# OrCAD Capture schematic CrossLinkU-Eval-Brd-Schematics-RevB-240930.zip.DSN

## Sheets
1 09 Revision History: title: Revision History; rev: 1.0; note: 305-PD-24-0940
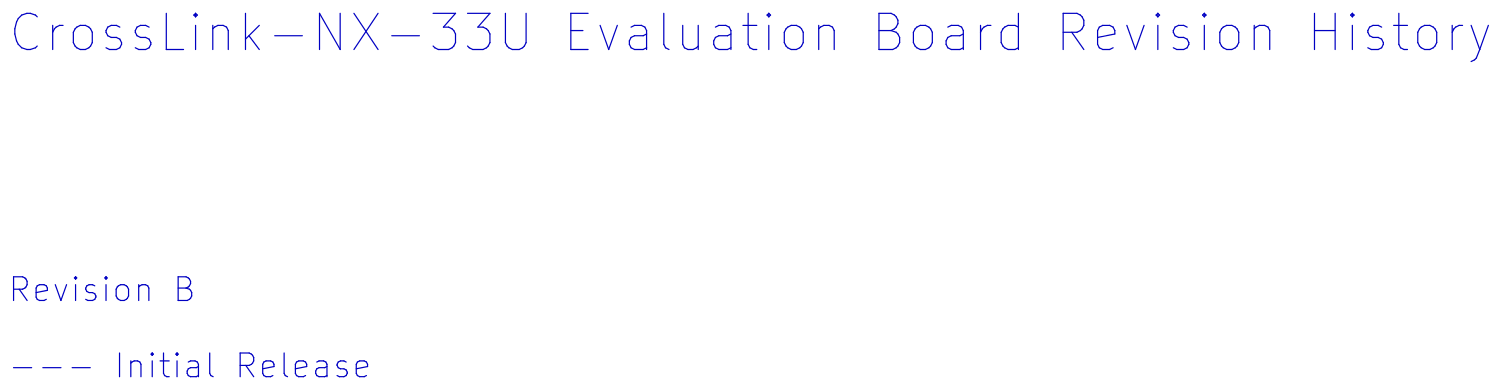
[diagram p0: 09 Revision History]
2 01 Title Page: title: Title Page
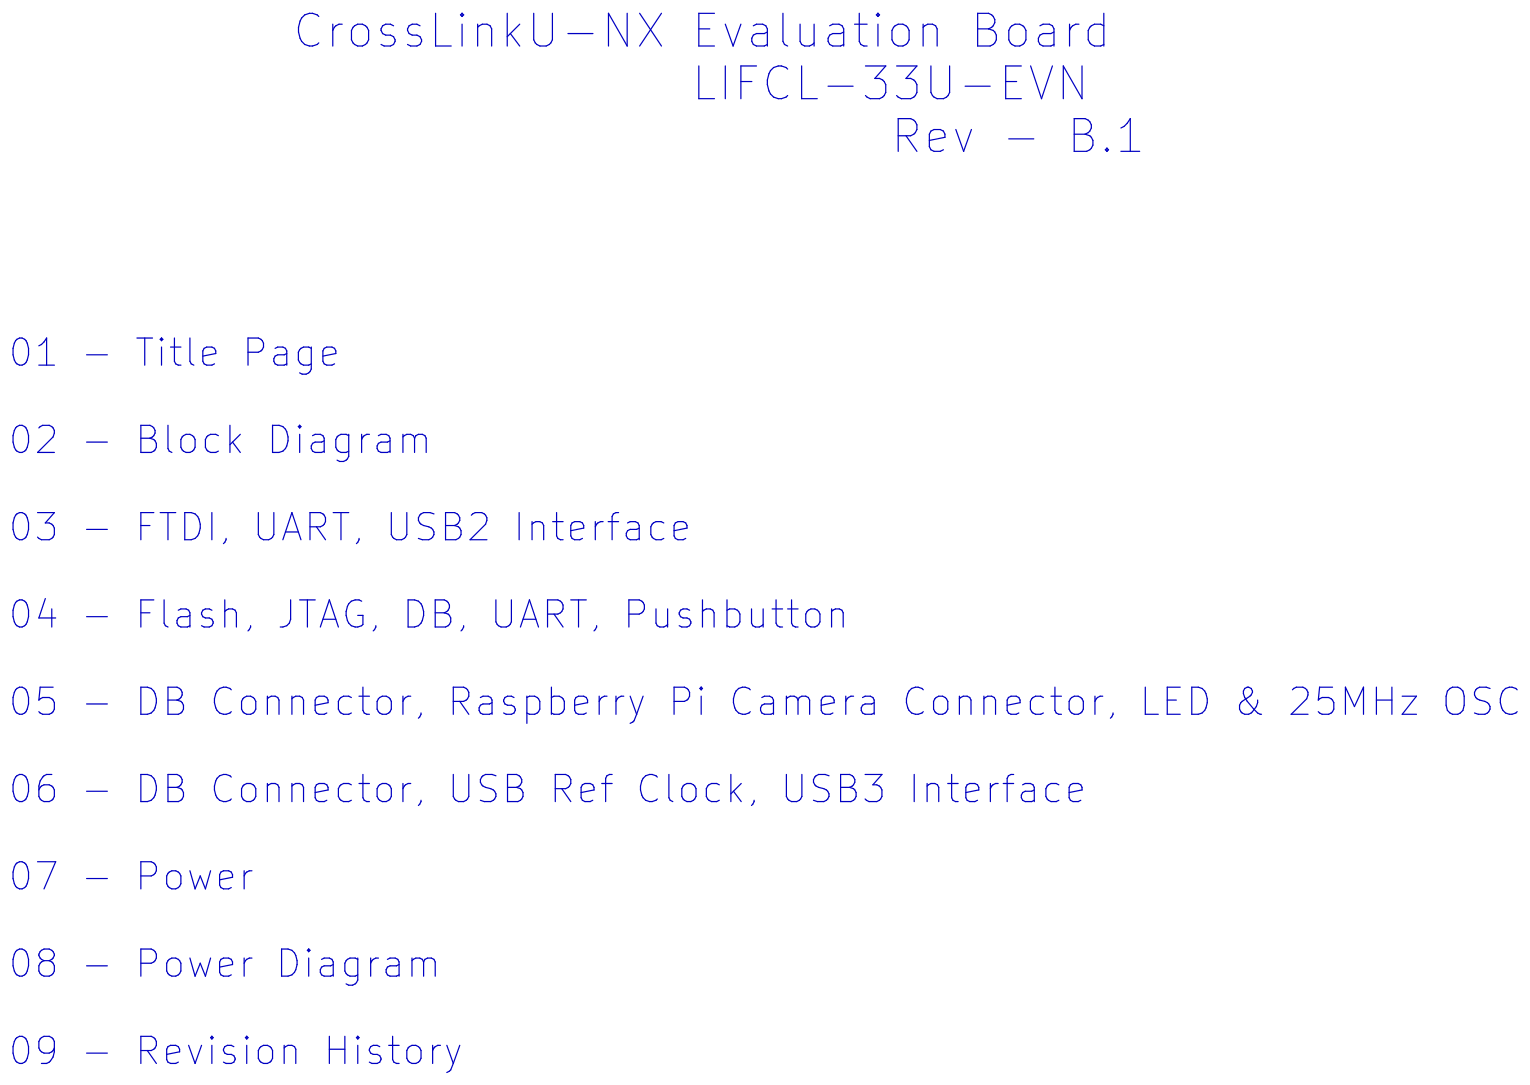
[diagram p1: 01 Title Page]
3 02 Block Diagram: title: Block Diagram
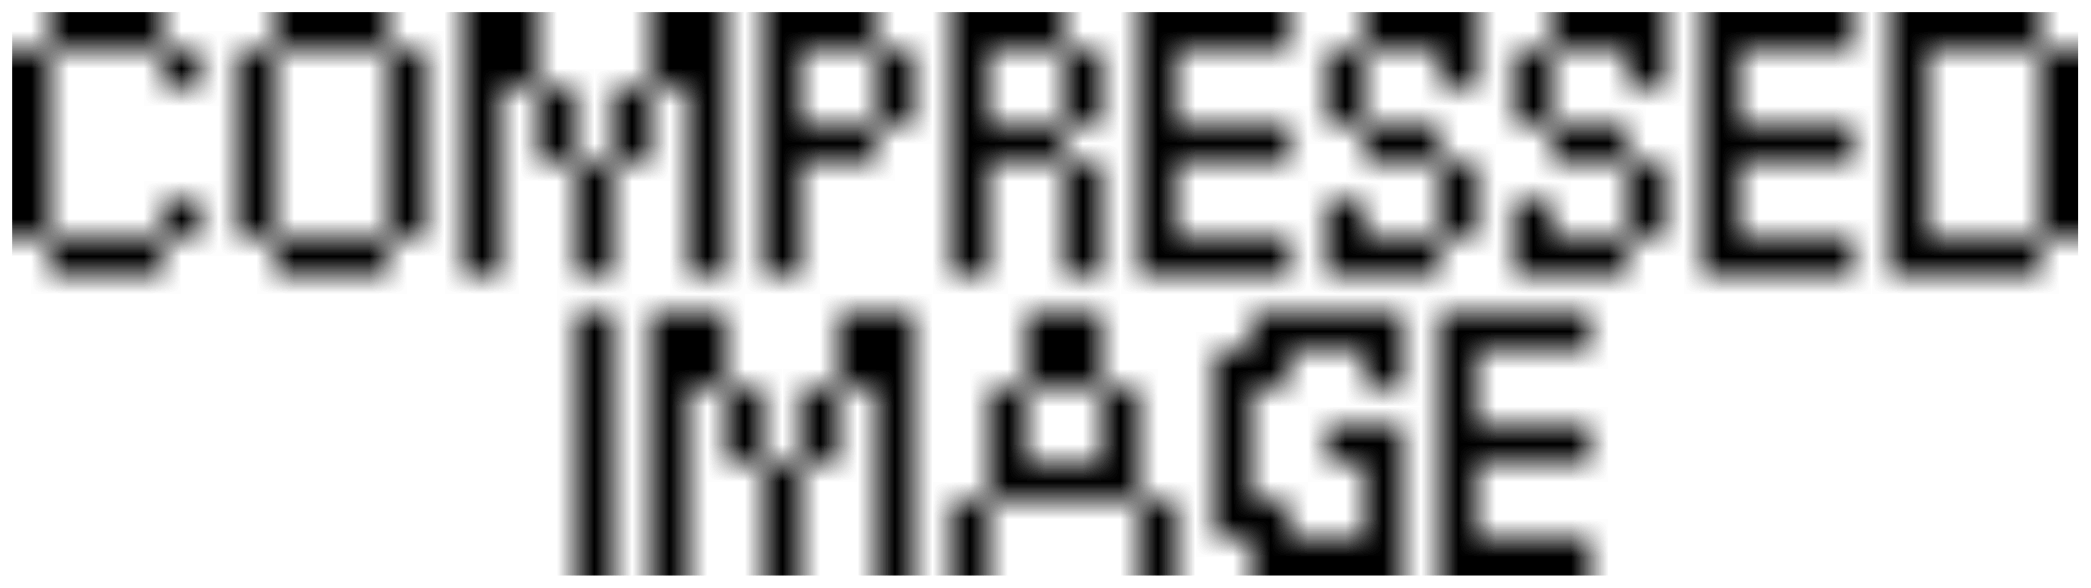
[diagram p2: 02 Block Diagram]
4 04 Flash, JTAG, LED, USB3, PMOD: size C; title: Flash, JTAG, DB, UART, Push Button
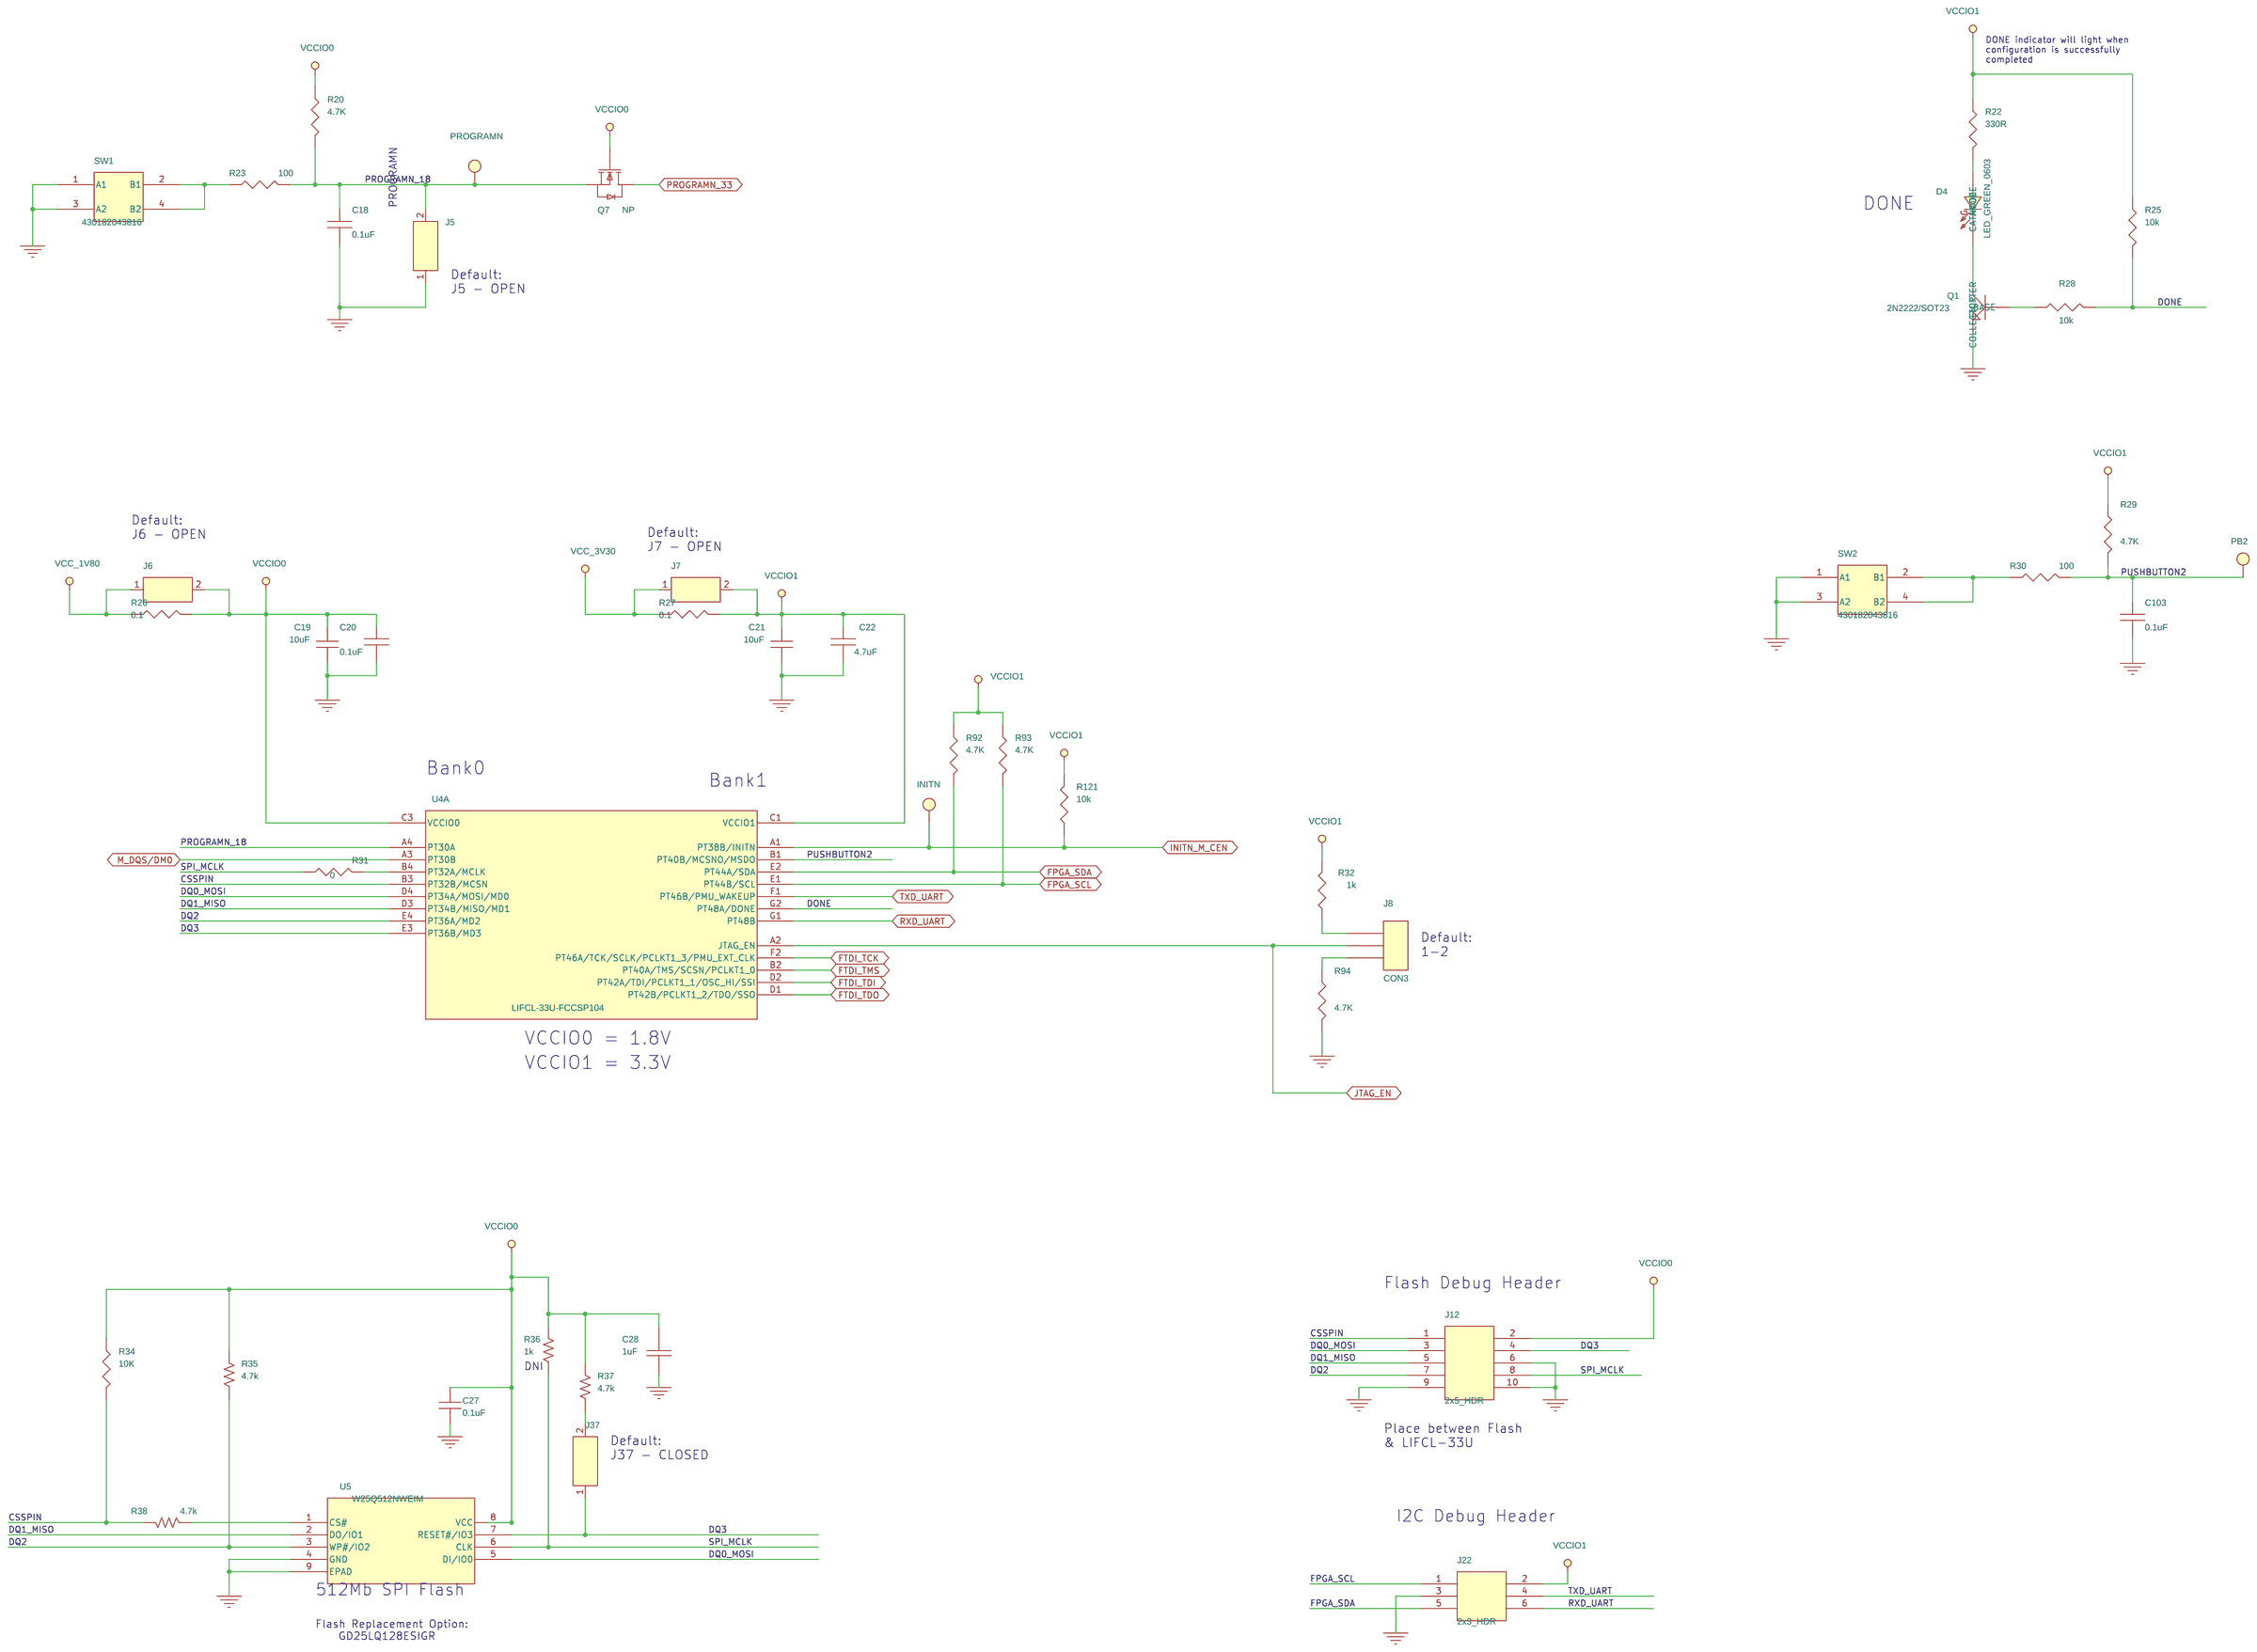
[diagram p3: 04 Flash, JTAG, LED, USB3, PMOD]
5 05 MIPI, PMOD: size C; title: DB Connector, Raspberry Pi Camera Connector, LED & 25MHz OSC
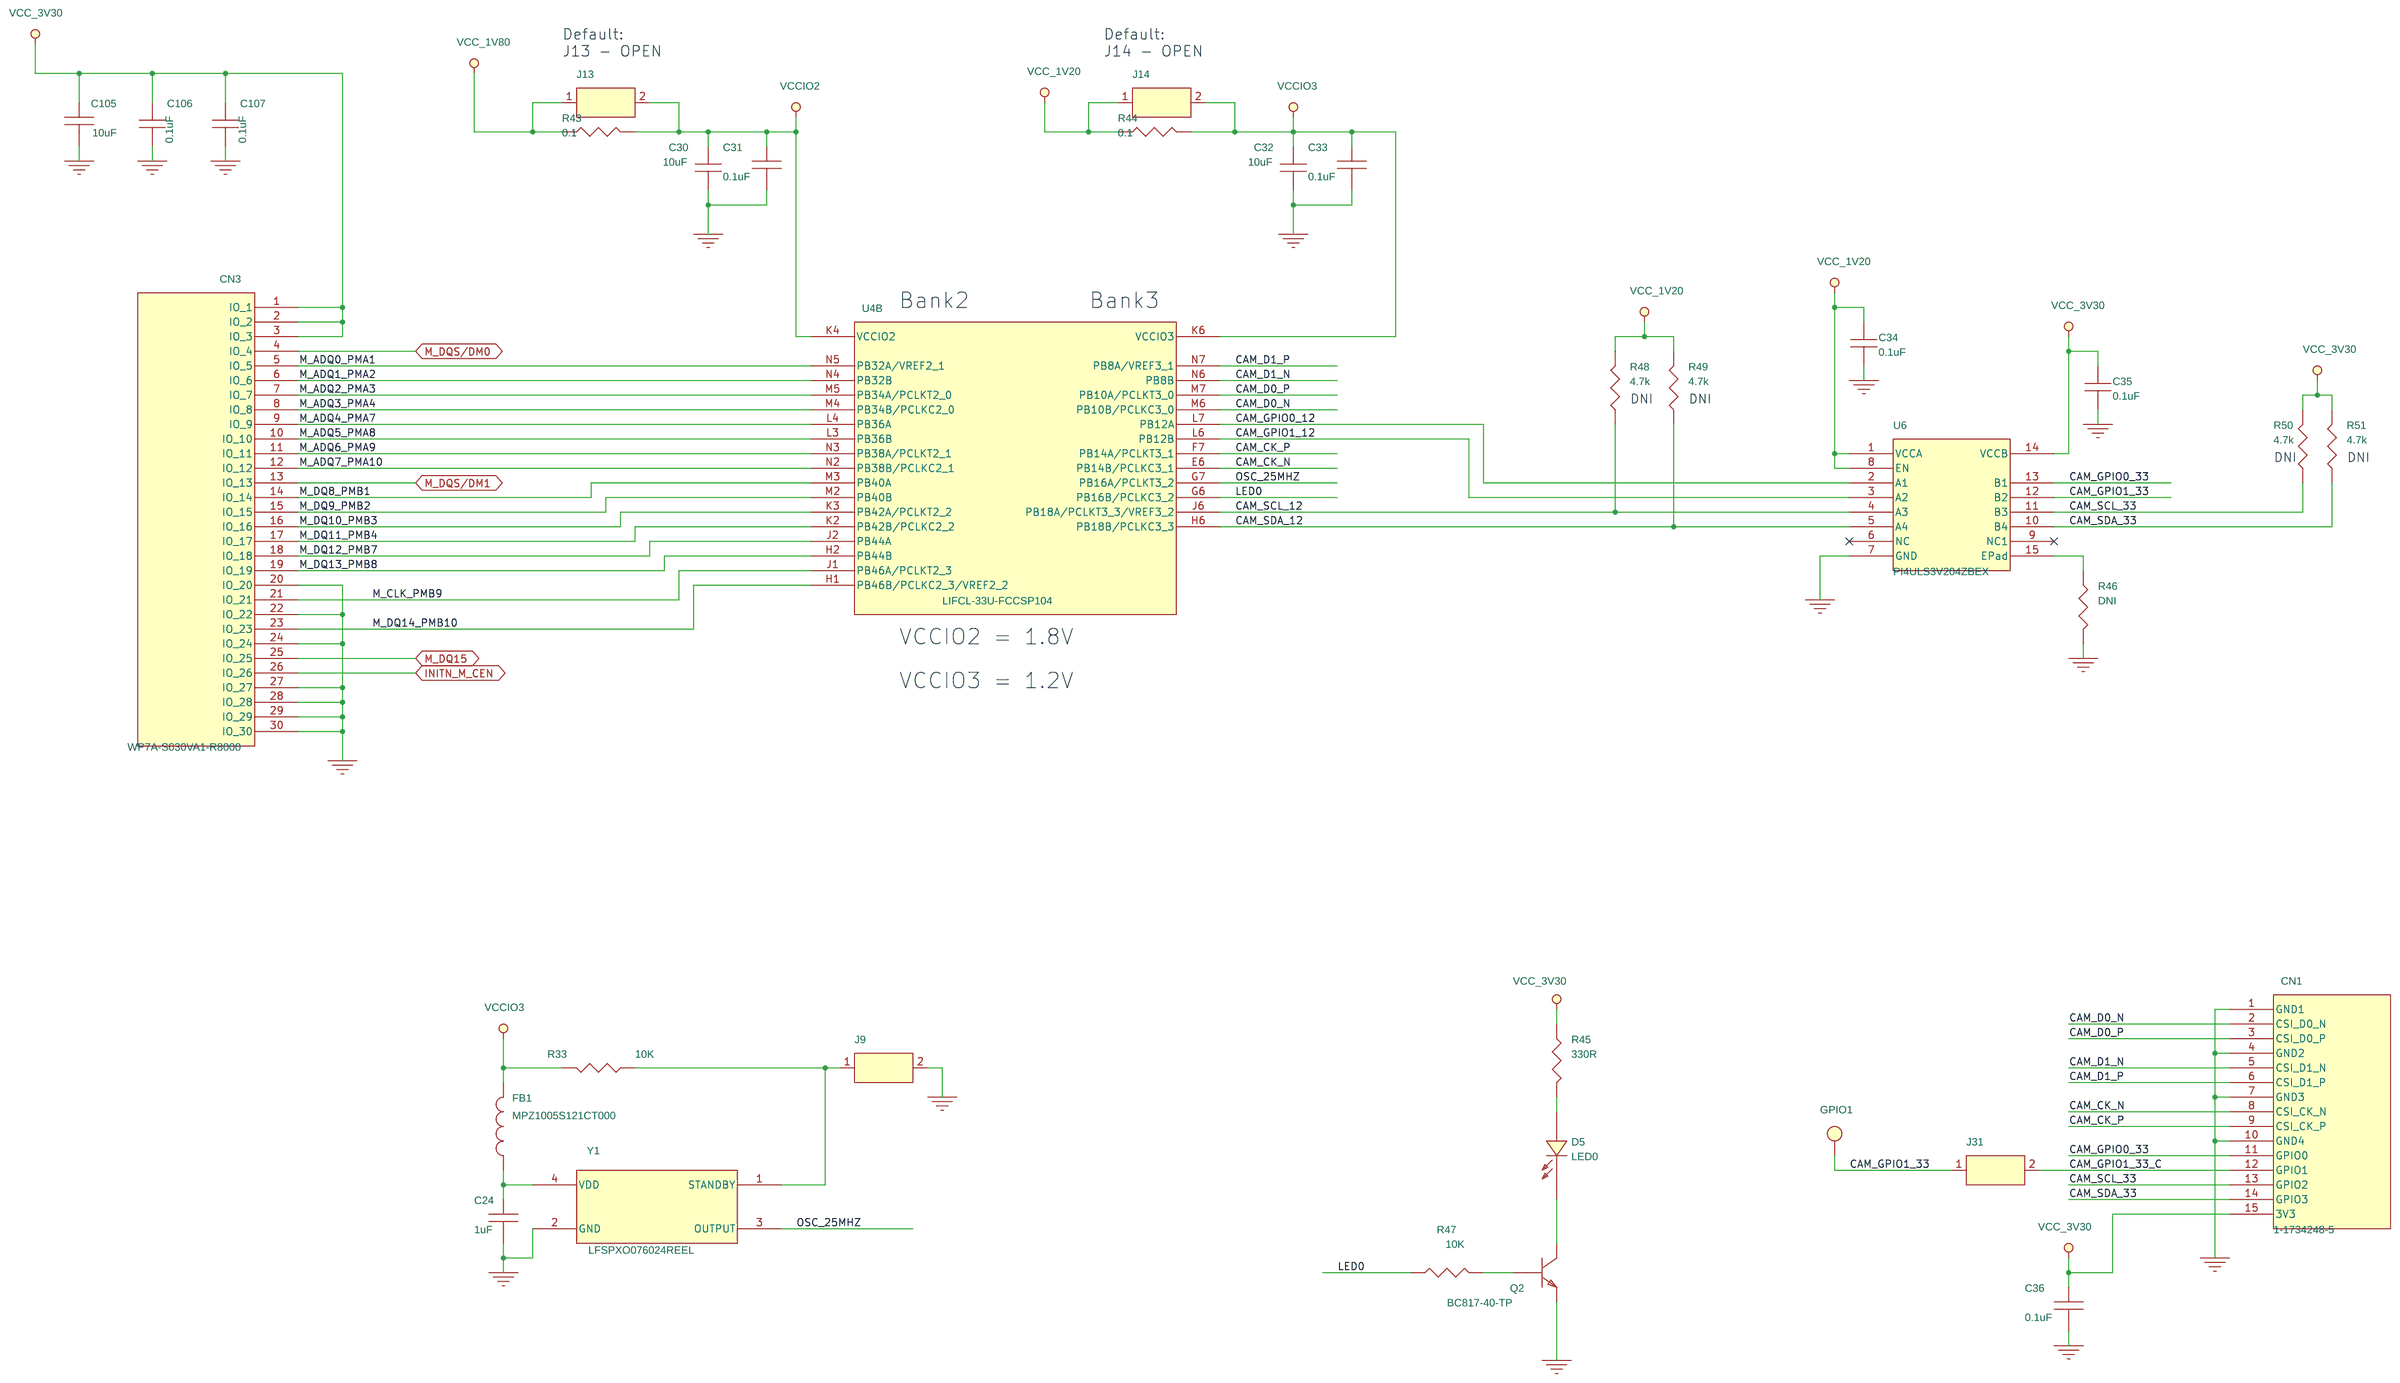
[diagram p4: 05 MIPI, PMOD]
6 06 USB3: size C; title: DB Connector, USB Ref Clock & USB3 Interface
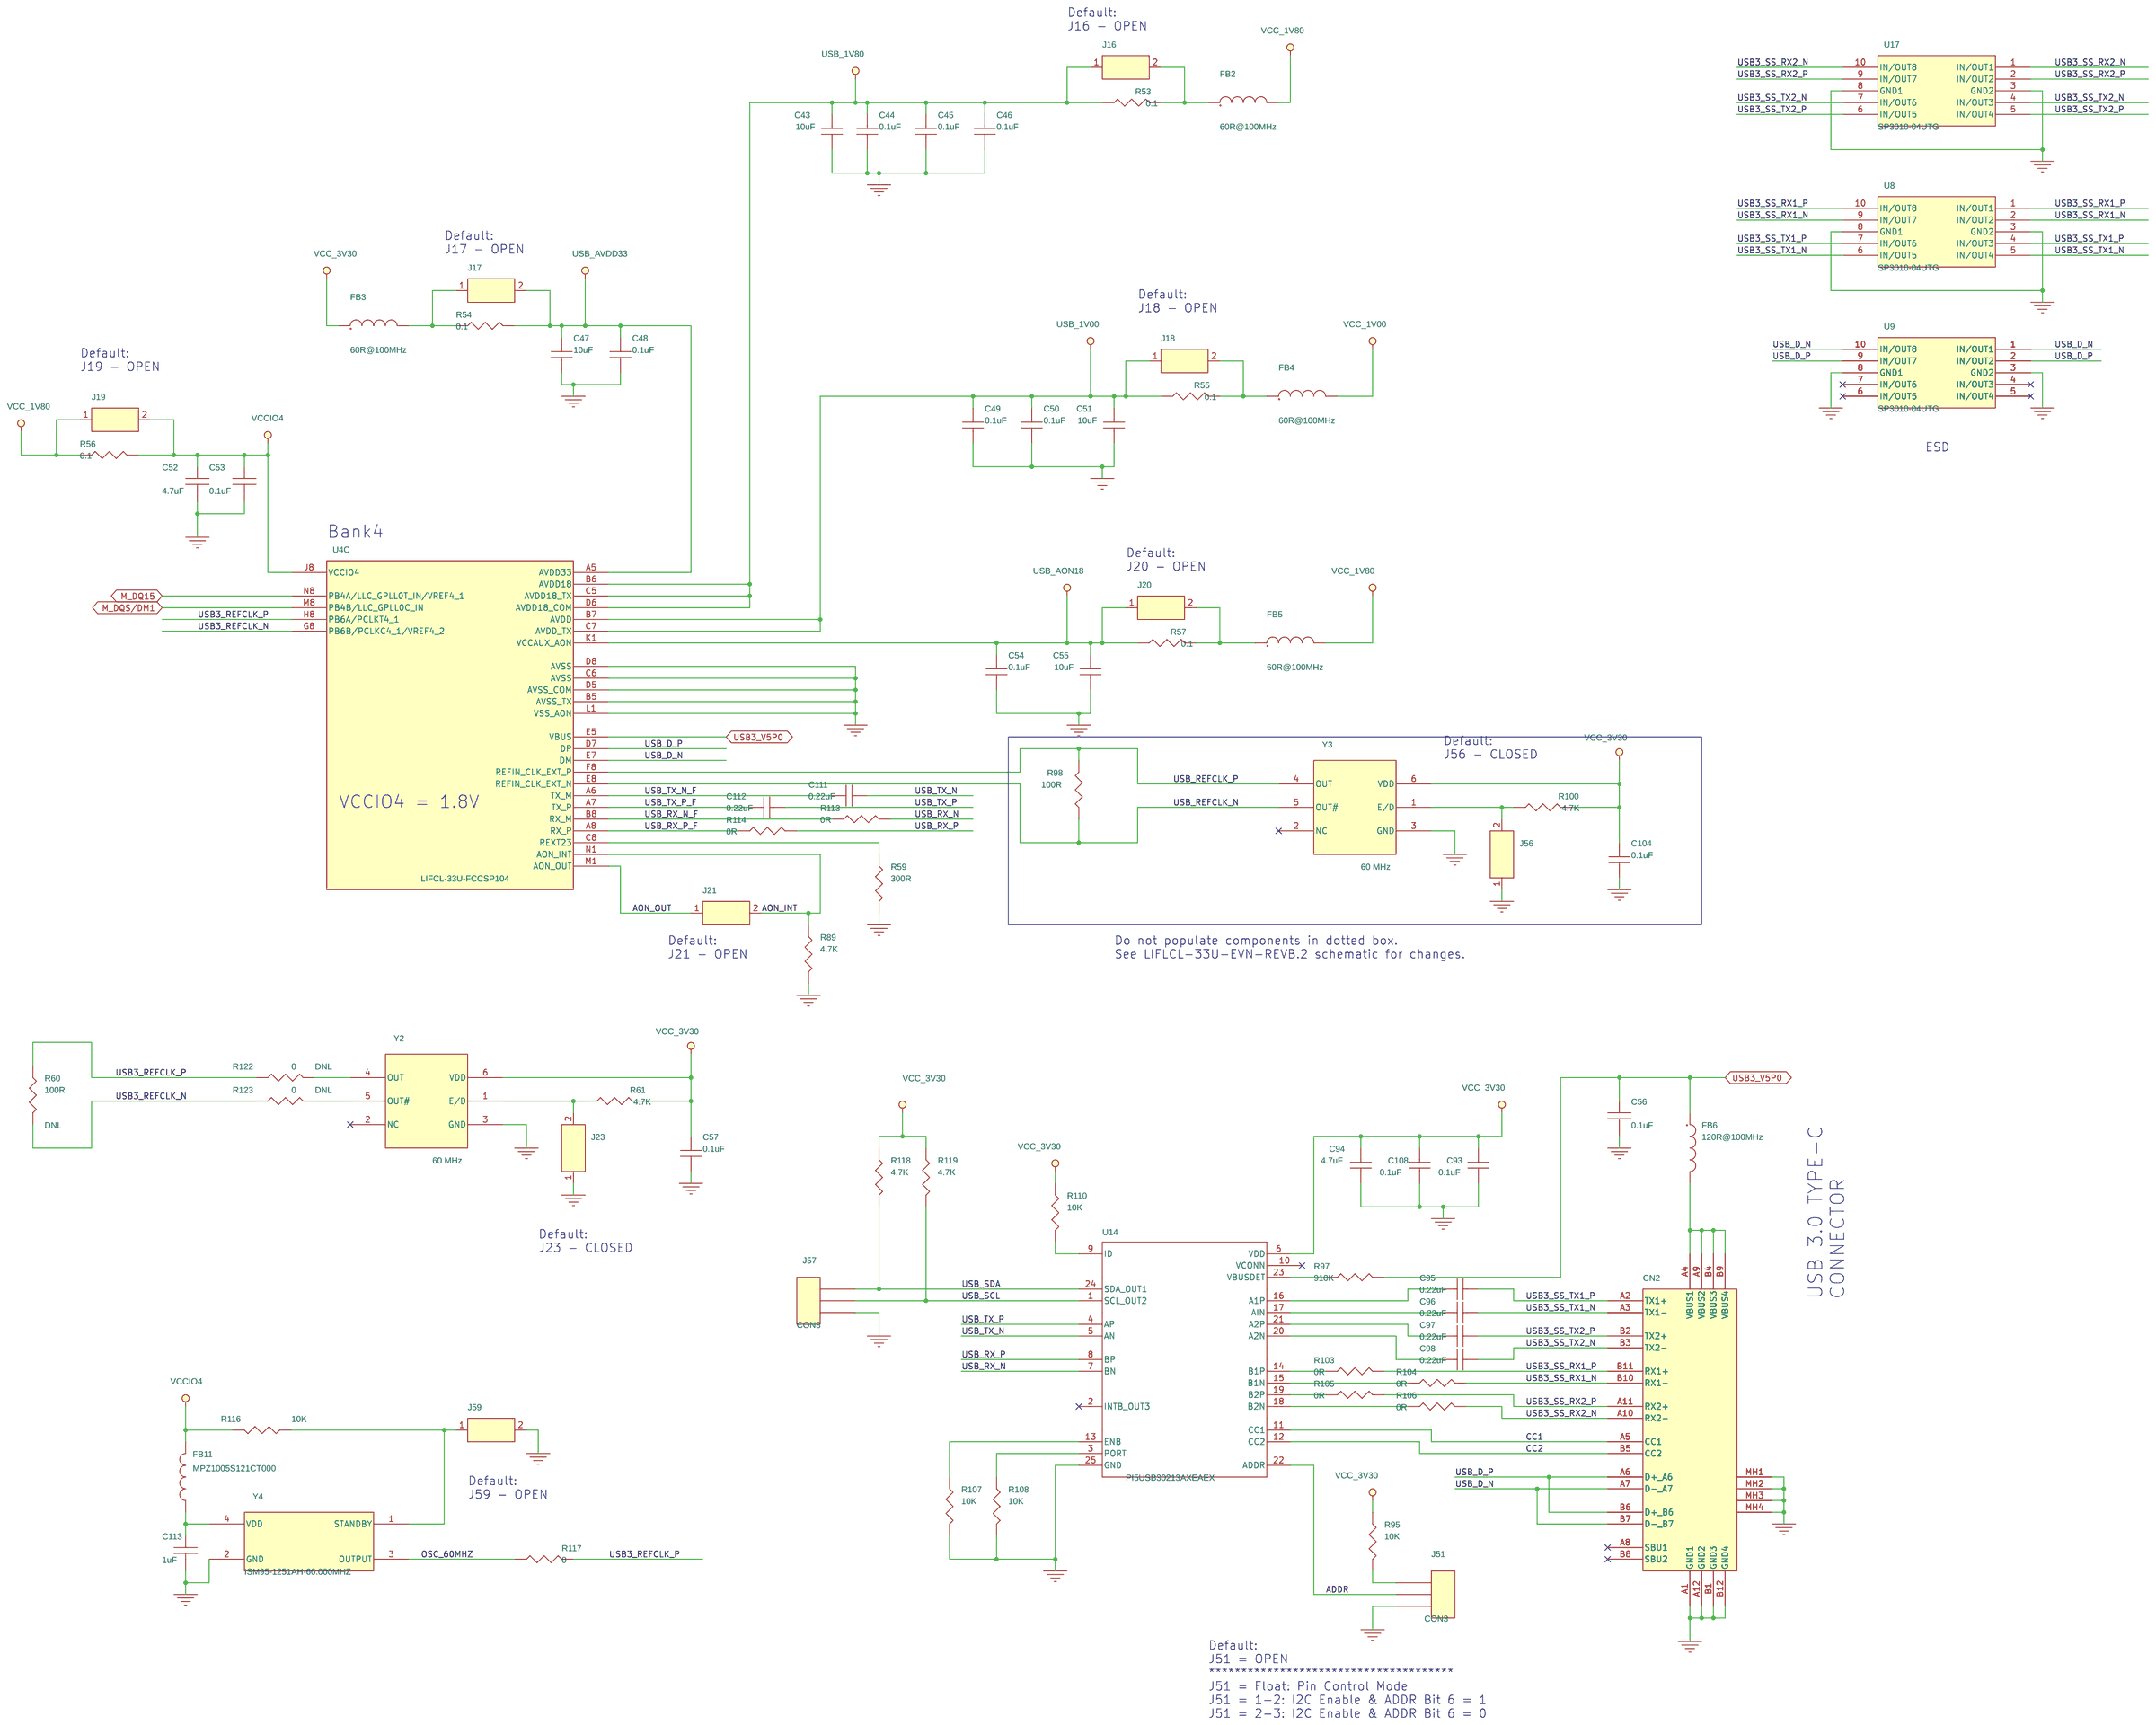
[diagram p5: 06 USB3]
7 07 Power: size C; title: Power
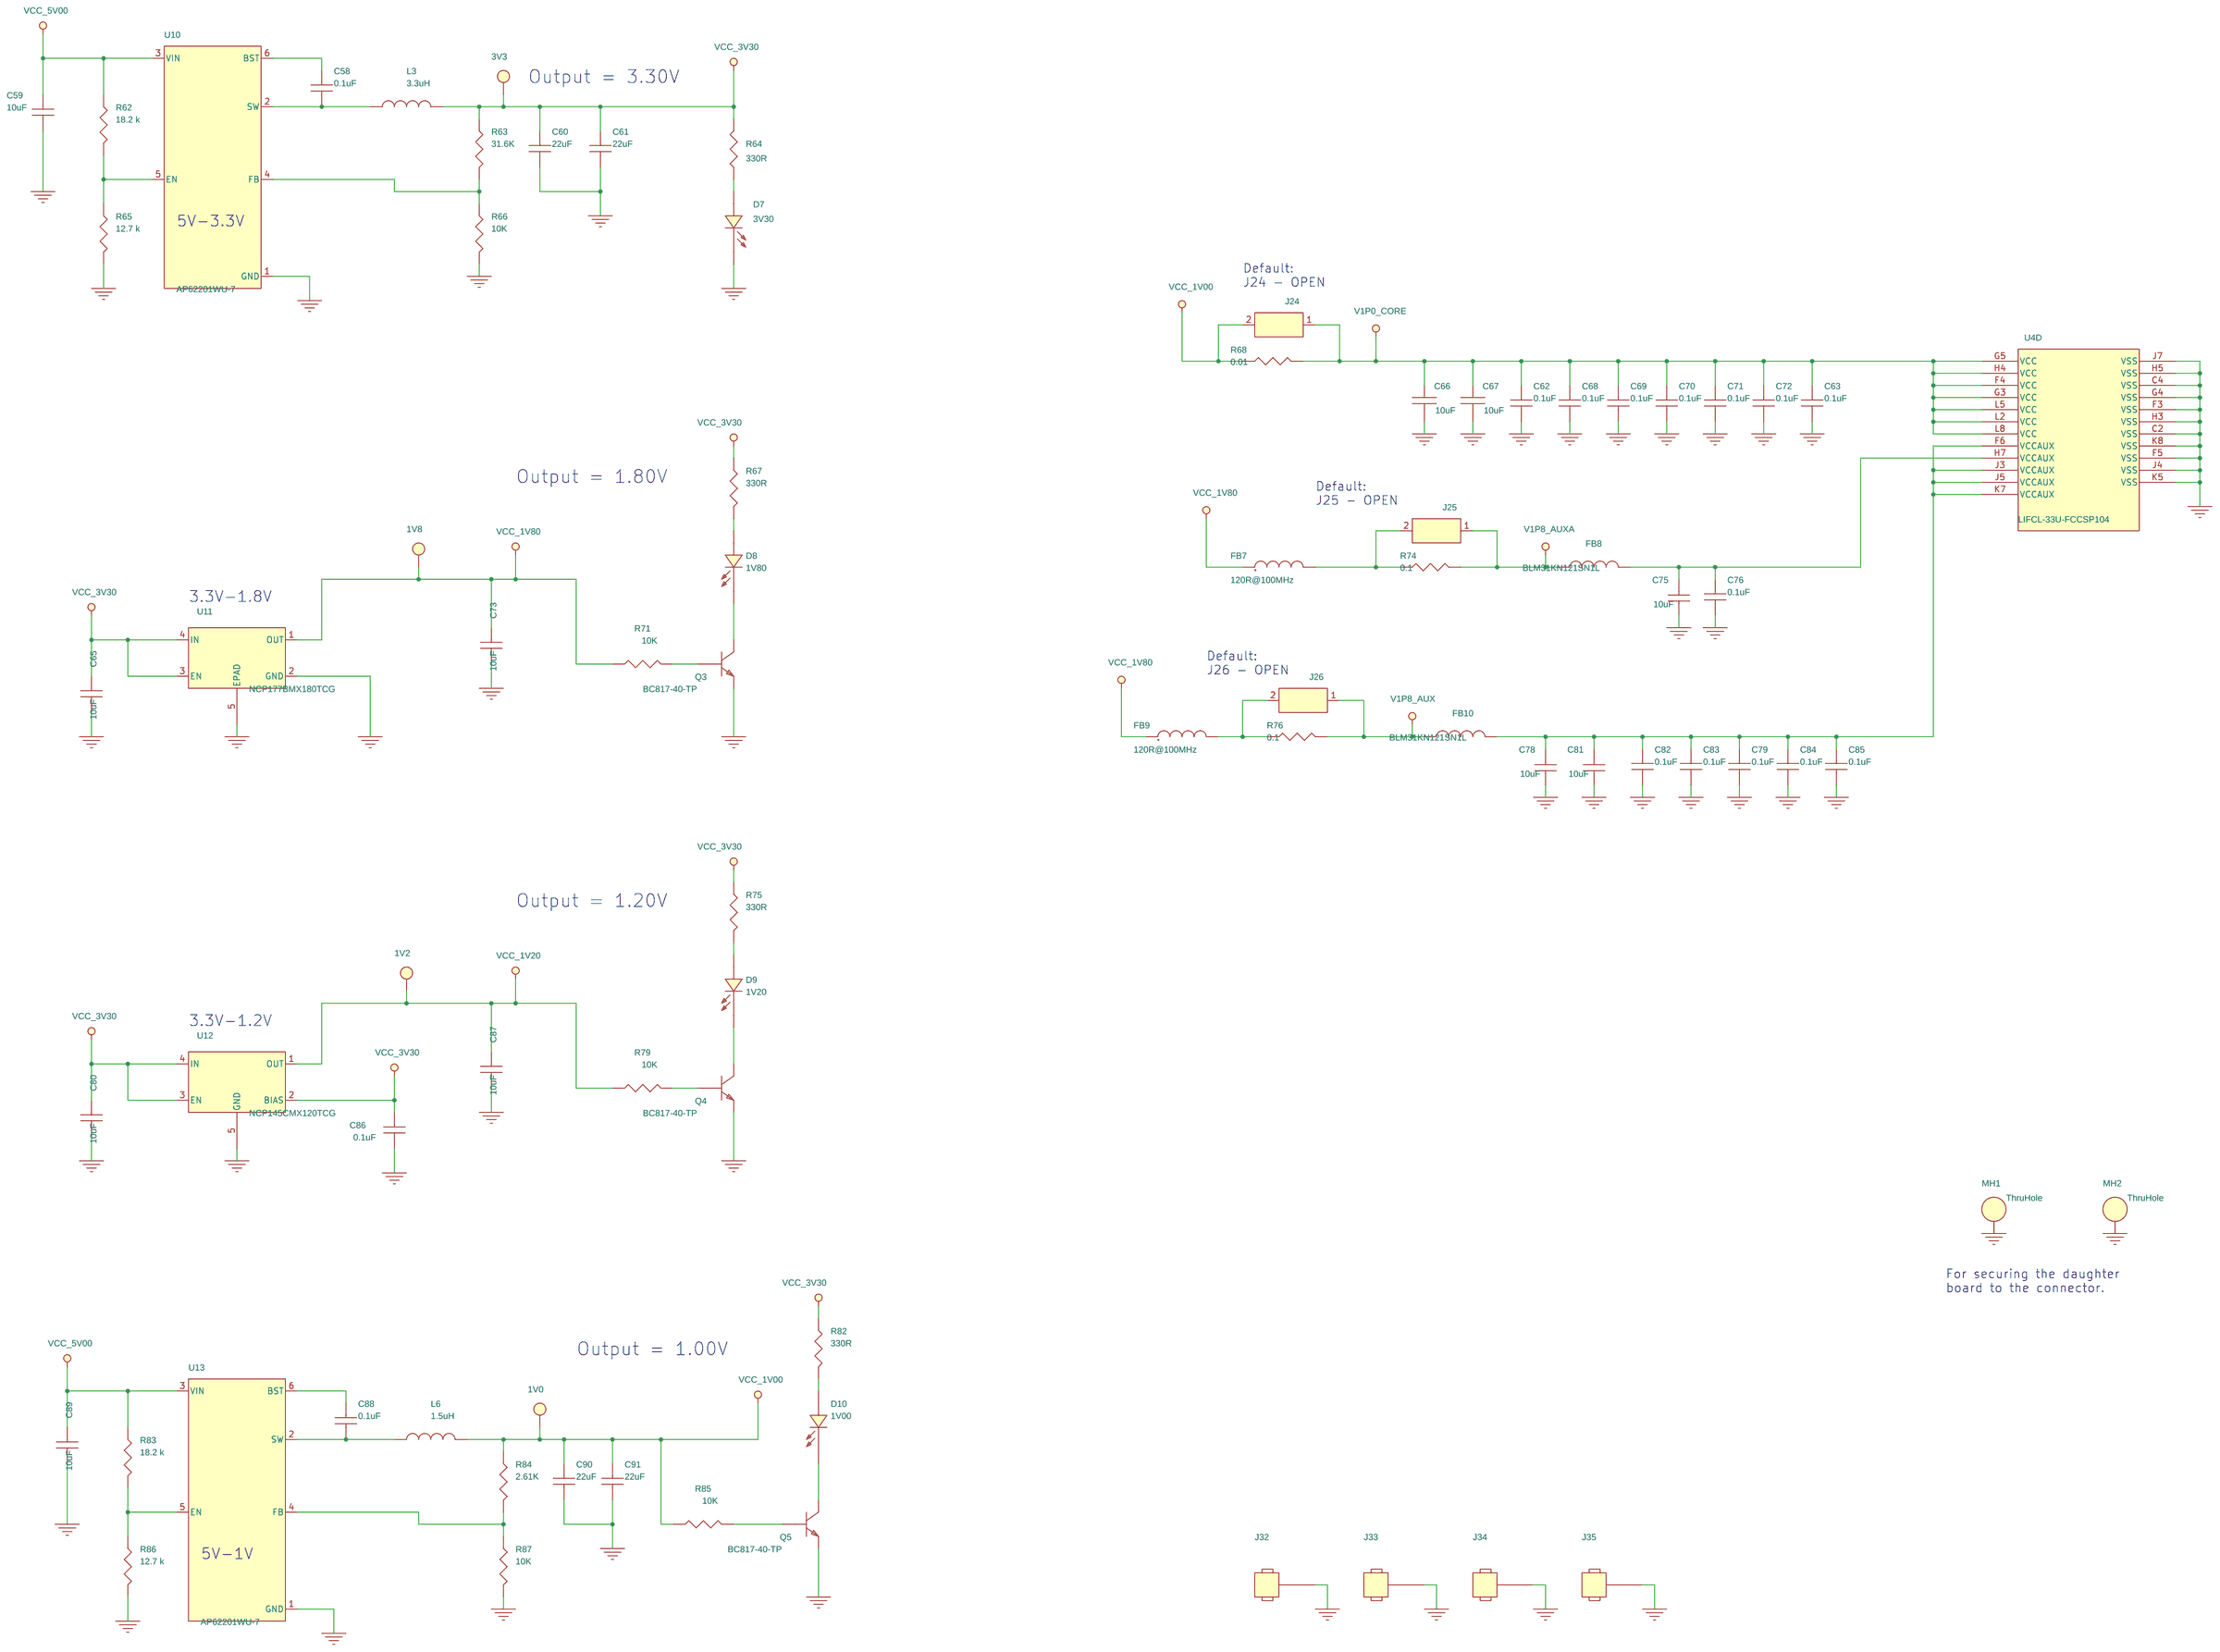
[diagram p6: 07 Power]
8 08 Power Diagram: title: Power Diagram
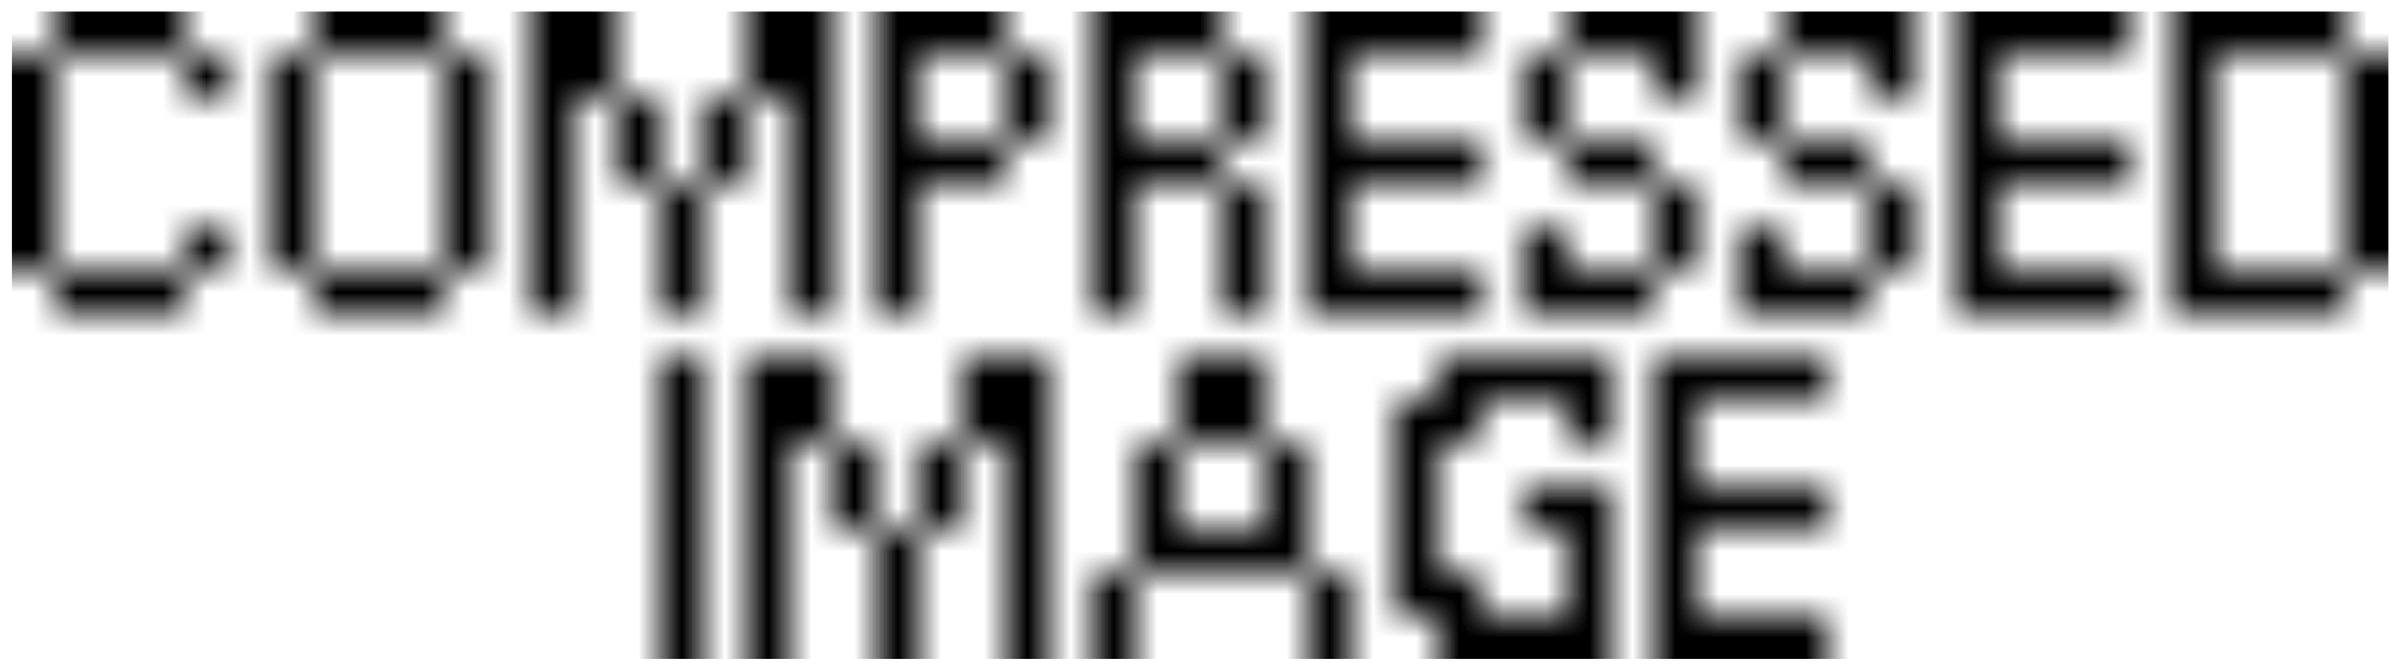
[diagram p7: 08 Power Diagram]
9 03 FTDI/USB Interface: size B; title: FTDI, UART, USB2 Interface
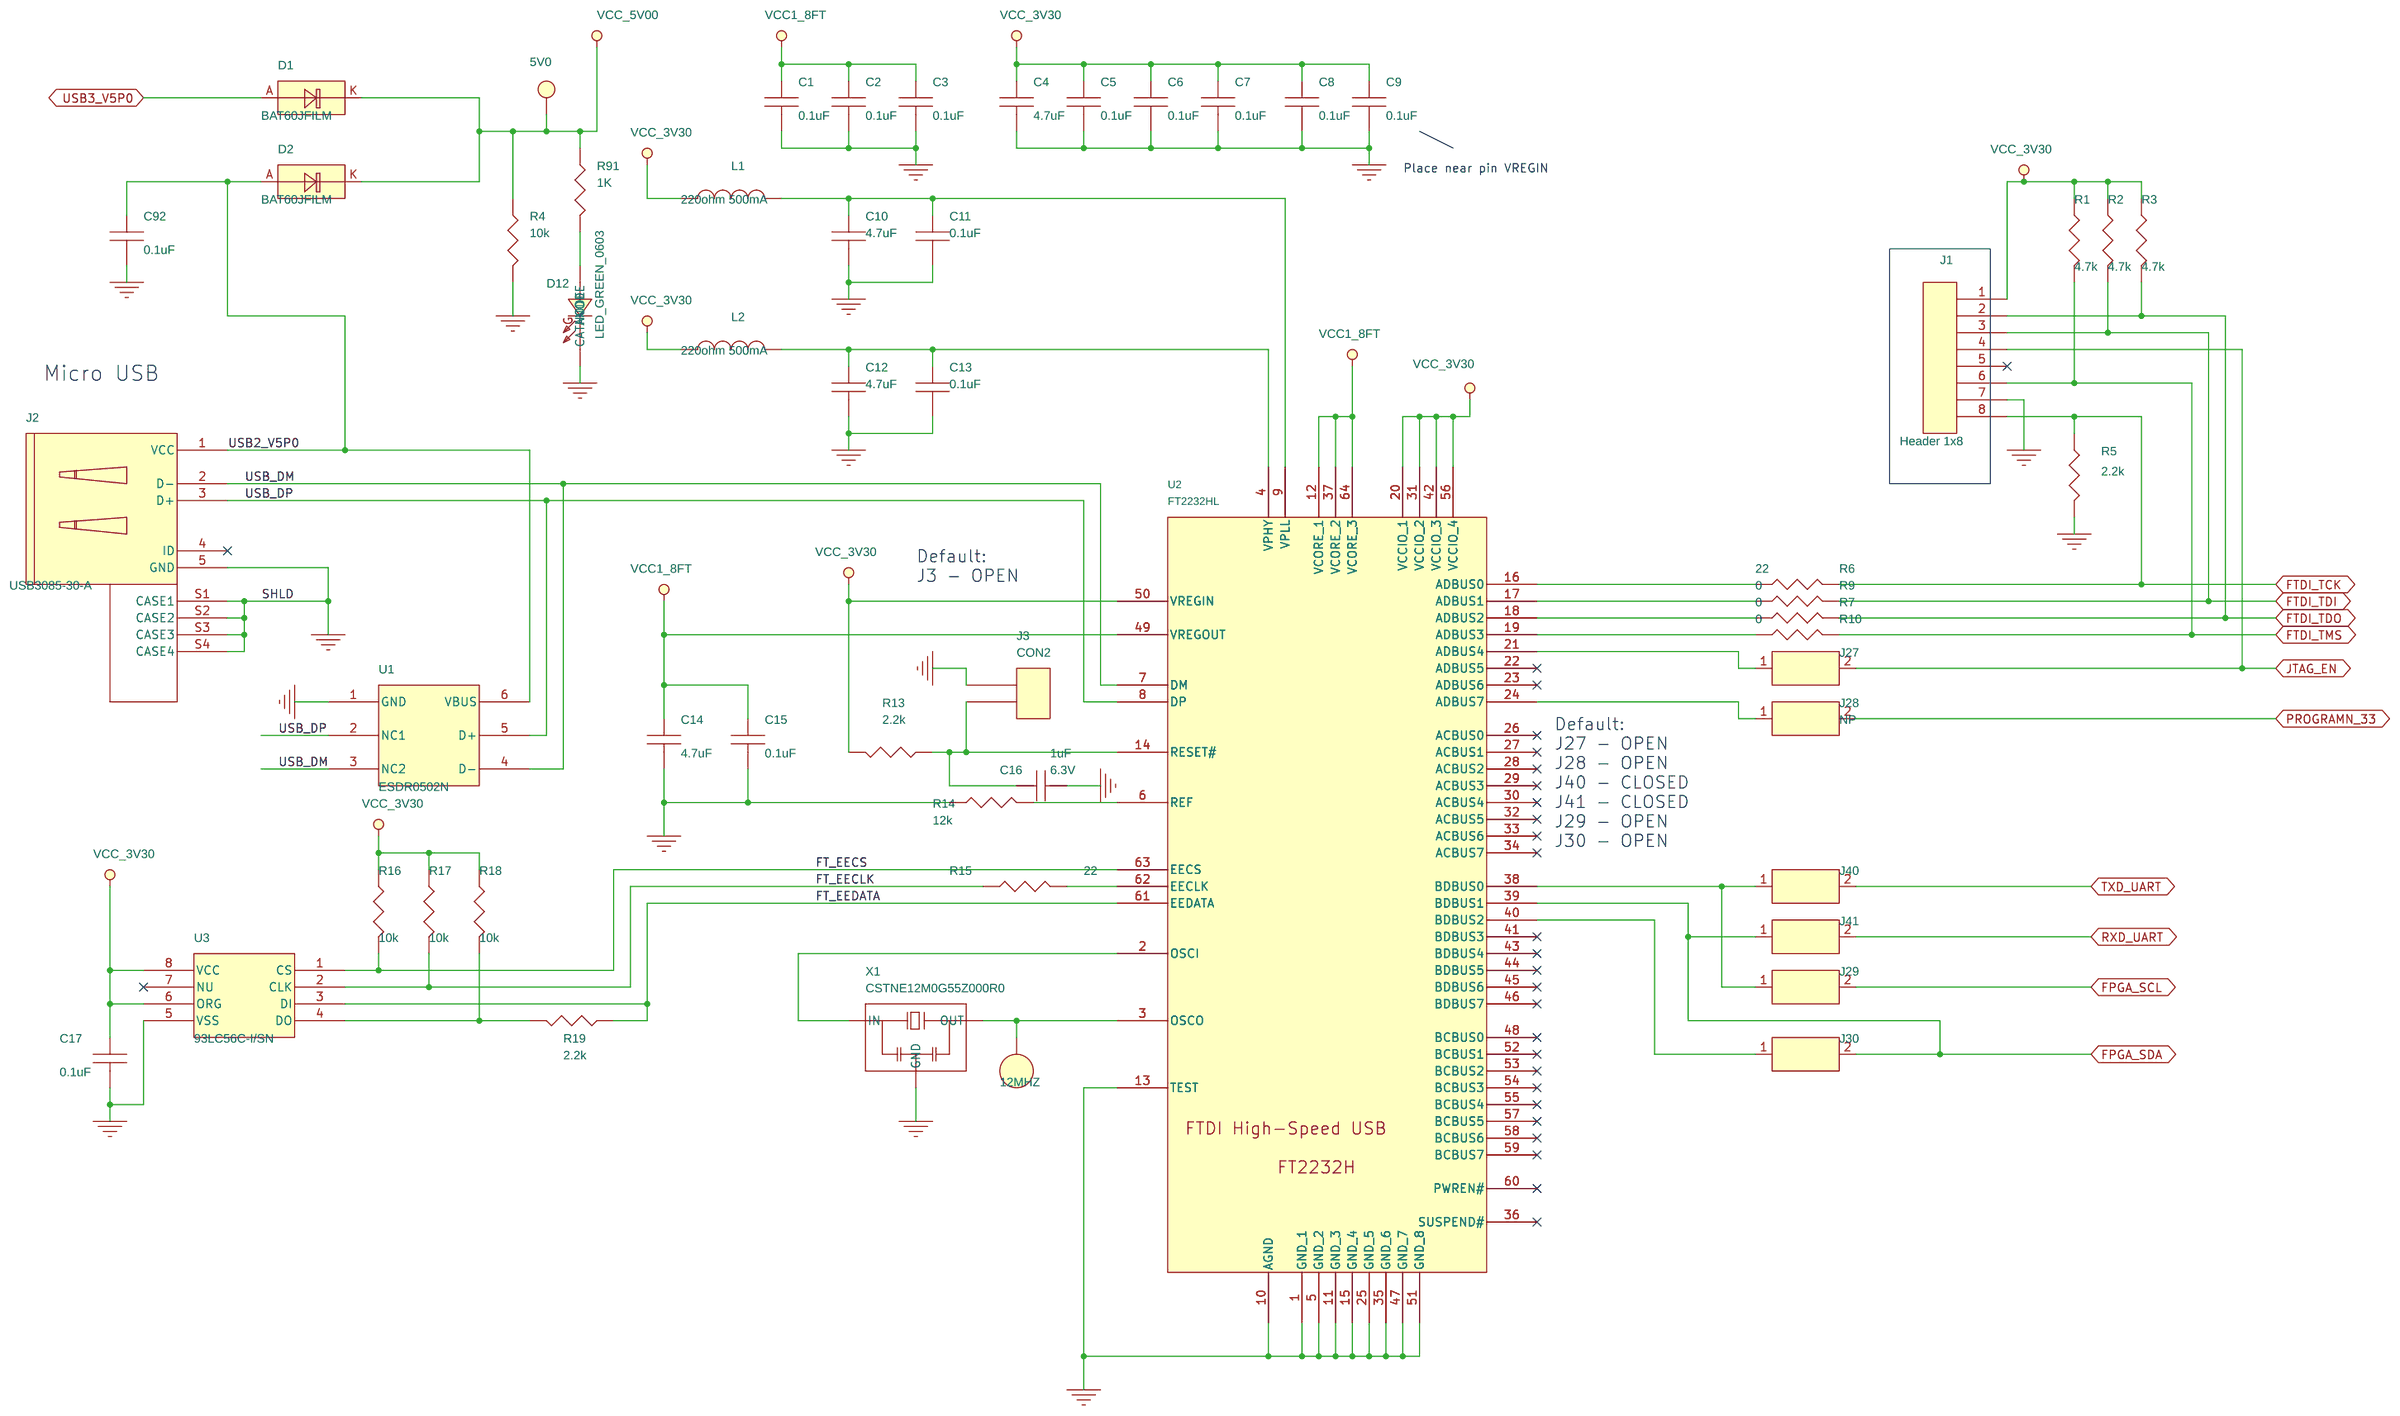
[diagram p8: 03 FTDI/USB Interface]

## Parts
sheet 03 FTDI/USB Interface
5V0  T POINT R  [TP]
12MHZ  T POINT R  [TP]
C1  0.1uF  [C0201]
C2  0.1uF  [C0201]
C3  0.1uF  [C0201]
C4  4.7uF  [C0402]
C5  0.1uF  [C0201]
C6  0.1uF  [C0201]
C7  0.1uF  [C0201]
C8  0.1uF  [C0201]
C9  0.1uF  [C0201]
C10  4.7uF  [C0402]
C11  0.1uF  [C0201]
C12  4.7uF  [C0402]
C13  0.1uF  [C0201]
C14  4.7uF  [C0402]
C15  0.1uF  [C0201]
C16  1uF  [C0402]
C17  0.1uF  [C0201]
C92  0.1uF  [C0201]
D1  BAT60JFILM  [SOD-323]
D2  BAT60JFILM  [SOD-323]
D12  LED_GREEN_0603  [APT1608]
J1  Header 1x8  [hdr_amp_87220_8_1x8_100]
J2  USB3085-30-A  [MICRO_AB_USB3085_30_A]
J3  CON2  [CON2]
J27  Header  [Header_2X1_100MIL]
J28  NP  [Header_2X1_100MIL]
J29  Header  [Header_2X1_100MIL]
J30  Header  [Header_2X1_100MIL]
J40  Header  [Header_2X1_100MIL]
J41  Header  [Header_2X1_100MIL]
L1  220ohm 500mA  [FB0402]
L2  220ohm 500mA  [FB0402]
R1  4.7k  [R0402]
R2  4.7k  [R0402]
R3  4.7k  [R0402]
R4  10k  [R0402]
R5  2.2k  [R0402]
R6  22  [R0402]
R7  0  [R0402]
R9  0  [R0402]
R10  0  [R0402]
R13  2.2k  [R0402]
R14  12k  [R0402]
R15  22  [R0402]
R16  10k  [R0402]
R17  10k  [R0402]
R18  10k  [R0402]
R19  2.2k  [R0402]
R91  1K  [R0402]
U1  ESDR0502N  [ESDR0502N]
U2  FT2232HL  [tqfp64_0p5_12p2x12p2_h1p6]
U3  93LC56C-I/SN  [so8_50_244]
X1  CSTNE12M0G55Z000R0  [OSC_CSTNE12M0G55Z000R0]
sheet 04 Flash, JTAG, LED, USB3, PMOD
C18  0.1uF  [C0201]
C19  10uF  [0402]
C20  0.1uF  [c0201_chamfer]
C21  10uF  [0402]
C22  4.7uF  [C0402]
C27  0.1uF  [C0201]
C28  1uF  [C0402]
C103  0.1uF  [C0201]
D4  LED_GREEN_0603  [APT1608]
INITN  T POINT R  [TP]
J5  Header  [Header_2X1_100MIL]
J6  Header  [Header_2X1_100MIL]
J7  Header  [Header_2X1_100MIL]
J8  CON3  [HDR1X3]
J12  2x5_HDR  [2X5_HDR]
J22  2x3_HDR  [2X3_HDR]
J37  Header  [Header_2X1_100MIL]
PB2  TestPoint_SMT  [TPC32]
PROGRAMN  TestPoint_SMT  [TPC32]
Q1  2N2222/SOT23  [MMBT2222ALT-1]
Q7  NP  [SOT-323]
R20  4.7K  [R0603]
R22  330R  [res0603]
R23  100  [R0402]
R25  10k  [R0402]
R26  0.1  [R0402]
R27  0.1  [R0402]
R28  10k  [R0402]
R29  4.7K  [R0603]
R30  100  [R0402]
R31  0  [R0402]
R32  1k  [R0402]
R34  10K  [R0402]
R35  4.7k  [R0402]
R36  1k  [R0402]
R37  4.7k  [R0402]
R38  4.7k  [R0402]
R92  4.7K  [R0402]
R93  4.7K  [R0402]
R94  4.7K  [R0603]
R121  10k  [R0402]
SW1  430182043816  [430182043816]
SW2  430182043816  [430182043816]
U5  W25Q512NWEIM  [8-WSON]
sheet 05 MIPI, PMOD
C24  1uF  [C0603]
C30  10uF  [0402]
C31  0.1uF  [c0201_chamfer]
C32  10uF  [0402]
C33  0.1uF  [c0201_chamfer]
C34  0.1uF  [C0402]
C35  0.1uF  [C0402]
C36  0.1uF  [c0201_chamfer]
C105  10uF  [C0402]
C106  0.1uF  [c0201_chamfer]
C107  0.1uF  [c0201_chamfer]
CN1  1-1734248-5  [15P_Connector]
CN3  WP7A-S030VA1-R8000  [WP7A-S030VA1-R8000]
D5  LED0  [led_0603]
FB1  MPZ1005S121CT000  [FB0402]
GPIO1  TestPoint  [TP50]
J9  Header  [Header_2X1_100MIL]
J13  Header  [Header_2X1_100MIL]
J14  Header  [Header_2X1_100MIL]
J31  Header  [Header_2X1_100MIL]
Q2  BC817-40-TP  [SOT23-3]
R33  10K  [R0603]
R43  0.1  [R0402]
R44  0.1  [R0402]
R45  330R  [res0603]
R46  DNI  [R0402]
R47  10K  [res0603]
R48  4.7k  [R0402]
R49  4.7k  [R0402]
R50  4.7k  [R0402]
R51  4.7k  [R0402]
U4  LIFCL-33U-FCCSP104  [FCCSP104]  (sections A,B,C,D)
U6  PI4ULS3V204ZBEX  [TQFN-14]
Y1  LFSPXO076024REEL  [4-SMD_25MHz]
sheet 06 USB3
C43  10uF  [C0402]
C44  0.1uF  [C0201]
C45  0.1uF  [C0201]
C46  0.1uF  [C0201]
C47  10uF  [C0402]
C48  0.1uF  [C0201]
C49  0.1uF  [C0201]
C50  0.1uF  [C0201]
C51  10uF  [C0402]
C52  4.7uF  [C0402]
C53  0.1uF  [c0201_chamfer]
C54  0.1uF  [C0201]
C55  10uF  [C0402]
C56  0.1uF  [C0201]
C57  0.1uF  [C0201]
C93  0.1uF  [C0402]
C94  4.7uF  [C0402]
C95  0.22uF  [0201]
C96  0.22uF  [0201]
C97  0.22uF  [0201]
C98  0.22uF  [0201]
C104  0.1uF  [C0201]
C108  0.1uF  [C0402]
C111  0.22uF  [0201]
C112  0.22uF  [0201]
C113  1uF  [C0603]
CN2  USB Type-C Receptacle  [usb_type_c]
FB2  60R@100MHz  [1806]
FB3  60R@100MHz  [1806]
FB4  60R@100MHz  [1806]
FB5  60R@100MHz  [1806]
FB6  120R@100MHz  [0805]
FB11  MPZ1005S121CT000  [FB0402]
J16  Header  [Header_2X1_100MIL]
J17  Header  [Header_2X1_100MIL]
J18  Header  [Header_2X1_100MIL]
J19  Header  [Header_2X1_100MIL]
J20  Header  [Header_2X1_100MIL]
J21  Header  [Header_2X1_100MIL]
J23  Header  [Header_2X1_100MIL]
J51  CON3  [HDR1X3]
J56  Header  [Header_2X1_100MIL]
J57  CON3  [HDR1X3]
J59  Header  [Header_2X1_100MIL]
R53  0.1  [R0402]
R54  0.1  [R0402]
R55  0.1  [R0402]
R56  0.1  [R0402]
R57  0.1  [R0402]
R59  300R  [0402]
R60  100R  [0201]
R61  4.7K  [R0402]
R89  4.7K  [R0402]
R95  10K  [R0402]
R97  910K  [0402]
R98  100R  [0201]
R100  4.7K  [R0402]
R103  0R  [R0201]
R104  0R  [R0201]
R105  0R  [R0201]
R106  0R  [R0201]
R107  10K  [R0402]
R108  10K  [R0402]
R110  10K  [R0402]
R113  0R  [R0201]
R114  0R  [R0201]
R116  10K  [R0603]
R117  0  [R0402]
R118  4.7K  [R0402]
R119  4.7K  [R0402]
R122  0  [R0402]
R123  0  [R0402]
U8  SP3010-04UTG  [UDFN10_SP3010-04UTG]
U9  SP3010-04UTG  [UDFN10_SP3010-04UTG]
U14  PI5USB30213AXEAEX  [QFN40P400X200X50-25N]
U17  SP3010-04UTG  [UDFN10_SP3010-04UTG]
Y2  60 MHz  [6SMD]
Y3  60 MHz  [6SMD]
Y4  ISM95-1251AH-60.000MHZ  [4-SMD_60MHz]
sheet 07 Power
1V0  T POINT R  [TP]
1V2  T POINT R  [TP]
1V8  T POINT R  [TP]
3V3  T POINT R  [TP]
C58  0.1uF  [cap0402]
C59  10uF  [C0603]
C60  22uF  [C0603]
C61  22uF  [C0603]
C62  0.1uF  [C0201]
C63  0.1uF  [C0201]
C65  10uF  [cap0805]
C66  10uF  [C0603]
C67  10uF  [C0603]
C68  0.1uF  [C0201]
C69  0.1uF  [C0201]
C70  0.1uF  [C0201]
C71  0.1uF  [C0201]
C72  0.1uF  [C0201]
C73  10uF  [cap0805]
C75  10uF  [C0603]
C76  0.1uF  [C0201]
C78  10uF  [C0603]
C79  0.1uF  [C0201]
C80  10uF  [cap0805]
C81  10uF  [C0603]
C82  0.1uF  [C0201]
C83  0.1uF  [C0201]
C84  0.1uF  [C0201]
C85  0.1uF  [C0201]
C86  0.1uF  [C0402]
C87  10uF  [cap0805]
C88  0.1uF  [cap0402]
C89  10uF  [cap0805]
C90  22uF  [C0603]
C91  22uF  [C0603]
D7  3V30  [led_0603]
D8  1V80  [led_0603]
D9  1V20  [led_0603]
D10  1V00  [led_0603]
FB7  120R@100MHz  [0805]
FB8  BLM31KN121SN1L  [BLM41P]
FB9  120R@100MHz  [0805]
FB10  BLM31KN121SN1L  [BLM41P]
J24  Header  [Header_2X1_100MIL]
J25  Header  [Header_2X1_100MIL]
J26  Header  [Header_2X1_100MIL]
J32  J-Turret  [TUR_TH]
J33  J-Turret  [TUR_TH]
J34  J-Turret  [TUR_TH]
J35  J-Turret  [TUR_TH]
L3  3.3uH  [0806]
L6  1.5uH  [0806]
MH1  ThruHole  [MTG125]
MH2  ThruHole  [MTG125]
Q3  BC817-40-TP  [SOT23-3]
Q4  BC817-40-TP  [SOT23-3]
Q5  BC817-40-TP  [SOT23-3]
R62  18.2 k  [res0402]
R63  31.6K  [0603]
R64  330R  [res0603]
R65  12.7 k  [res0402]
R66  10K  [0603]
R67  330R  [res0603]
R68  0.01  [R0402]
R71  10K  [res0603]
R74  0.1  [R0402]
R75  330R  [res0603]
R76  0.1  [R0402]
R79  10K  [res0603]
R82  330R  [res0603]
R83  18.2 k  [res0402]
R84  2.61K  [0603]
R85  10K  [res0603]
R86  12.7 k  [res0402]
R87  10K  [0603]
U10  AP62201WU-7  [TSOT26_AP62201WU-7]
U11  NCP177BMX180TCG  [XDFN4]
U12  NCP145CMX120TCG  [XDFN4]
U13  AP62201WU-7  [TSOT26_AP62201WU-7]

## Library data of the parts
1V0 1V2 1V8 3V3 5V0 INITN = T_POINT_R_0_v2: Assy: DNL; COMPFIXED: NO; COMPGROUP: 0; COMPHEIGHT: 0.000; COMPKEY: NO; COMPLOCKED: NO; COMPROT: 0; COMPSIDE: TOP; DECOUPLER: NO; MEMORY: NO
12MHZ = T_POINT_R_0: Assy: DNL; COMPFIXED: NO; COMPGROUP: 0; COMPHEIGHT: 0.000; COMPKEY: NO; COMPLOCKED: NO; COMPROT: 0; COMPSIDE: TOP; DECOUPLER: NO; MEMORY: NO
C1-C3 C5-C9 C11 C13 C15 C17 C20 C31 C33 C36 C53 = 0u1_0402: CAP CER 0.1UF 16V X5R 0201; Digikey P/N: 445-7313-2-ND; Manufacturer: TDK; Manufacturer Part Number: C0603X5R1C104K030BC
C4 C14 C22 C52 = 10uF_0603: CAP CER 4.7UF 10V X5R 0402; Digikey P/N: 445-13820-2-ND; Manufacturer: TDK; Manufacturer Part Number: C1005X5R1A475K050BC
C10 C12 = 4u7_0603: CAP CER 4.7UF 10V X5R 0402; Digikey P/N: 445-13820-2-ND; Manufacturer: TDK; Manufacturer Part Number: C1005X5R1A475K050BC
C16 = CAP_CER_100nF_0402_10V: CAP CER 1UF 16V X5R 0402; Digikey P/N: 587-3709-2-ND; Manufacturer: Taiyo Yuden; Manufacturer Part Number: EMK105BJ105KVHF; Voltage: 6.3V
C56 C92 = 0u1_0402: CAP CER 0.1UF 25V 10% X5R 0201; Manufacturer: Murata; Manufacturer Part Number: GRM033R61E104KE14J
D1 D2 = D-BAT60JFILM_0: Manufacturer: STMicroelectronics
D4 D12 = LED-SMT1206_GREEN_1: LED GREEN CLEAR CHIP SMD; Digikey P/N: 754-1116-2-ND; Manufacturer: Kingbright; Manufacturer Part Number: APT1608CGCK
J1 = header1x8_100: CONN HEADER 8POS .100 VERT TIN; Digikey P/N: WM50017-08-ND; Manufacturer Part Number: 0022284081
J2 = USB_MINI_B_5: USB - micro AB USB 2.0 Receptacle Connector 5 Position Surface Mount, Right Angle; Digikey P/N: WM17143TR-ND; Manufacturer: GCT
J3 = CON2: CONN HEADER VERT 2POS 2.54MM; Digikey P/N: 732-5315-ND; Manufacturer: Würth Elektronik; Manufacturer Part Number: 61300211121
J5-J7 J9 J13 J14 J16-J21 J23-J27 J29-J31 J37 J40 J41 J56 J59 = J-Header_2x1_v2
J28 = J-Header_2x1_v2_NP: Assy: DNL
L1 L2 = FB0603: FERRITE BEAD 220 OHM 0402 1LN; Digikey P/N: 445-9329-2-ND; Manufacturer: TDK Corporation; Manufacturer Part Number: MPZ1005S221ET000
R1-R3 = 5k1_0402: RES SMD 4.7K OHM 1% 1/16W 0402; Digikey P/N: 311-4.7KLRTR-ND; Manufacturer: Yageo; Manufacturer Part Number: RC0402FR-074K7L
R4 = 5k1_0402: RES SMD 10K OHM 1% 1/16W 0402; Digikey P/N: 311-10.0KLRTR-ND; Manufacturer: Yageo; Manufacturer Part Number: RC0402FR-0710KL
R5 R13 = 5k1_0402: RES SMD 2.2K OHM 1% 1/16W 0402; Digikey P/N: 311-2.20KLRTR-ND; Manufacturer: Yageo; Manufacturer Part Number: RC0402FR-072K2L
R6 = 0R_0603: RES SMD 33 OHM 1% 1/10W 0402; Manufacturer: Panasonic; Manufacturer Part Number: ERJ-2RKF33R0X
R7 R9 R10 = 0R_0603: RES 0.0 OHM 1/10W JUMP 0603 SMD
R14 = 10k_0402: RES SMD 12K OHM 1% 1/16W 0402; Digikey P/N: 311-12.0KLRTR-ND; Manufacturer: Yageo; Manufacturer Part Number: RC0402FR-0712KL
R15 = 0R_0603: RES SMD 22 OHM 1% 1/16W 0402; Digikey P/N: 311-22.0LRTR-ND; Manufacturer: Yageo; Manufacturer Part Number: RC0402FR-0722RL
R16-R18 = RES_10K_1W16_0402_5P: RES SMD 10K OHM 1% 1/16W 0402; Digikey P/N: 311-10.0KLRTR-ND; Manufacturer: Yageo; Manufacturer Part Number: RC0402FR-0710KL
R19 = 10k_0402: RES SMD 2.2K OHM 1% 1/16W 0402; Digikey P/N: 311-2.20KLRTR-ND; Manufacturer: Yageo; Manufacturer Part Number: RC0402FR-072K2L
R91 = R0402_1K_5%_VISHAY: Manufacturer: Vishay; Manufacturer Part Number: CRCW04021K00JNED
U1 = ESDR0502N_0: TVS DIODE 5.5VWM 6UDFN; Digikey P/N: 2156-ESDR0502NMUTBG-OS-ND; Manufacturer: ON Semiconductor; Manufacturer Part Number: ESDR0502NMUTBG
U2 = FT2232HL_3: IC USB HS DUAL UART/FIFO 64-LQFP
U3 = 93LC56_SO8_0: IC EEPROM 2KBIT SPI 3MHZ 8SOIC
X1 = CSTNE12M0G55Z000R0_0: CERAMIC RES 12.0000MHZ 33PF SMD; Digikey P/N: 490-17945-2-ND; Manufacturer: Murata Electronics
C18 C24 C103 C113 = 0u1_0402: CAP CER 0.1UF 16V 10% X7R 0402
C19 C21 C30 C32 C43 C47 C51 C55 = C-0402_10uF_6.3V_X5R_Murata: Manufacturer: Murata Electronics; Manufacturer Part Number: GRM155R60J106ME15D
C27 = CAP_NP: CAP CER 0.1UF 16V X5R 0201; DECOUPLER: NO; Digikey P/N: 445-7313-2-ND; MEMORY: NO; Manufacturer: TDK; Manufacturer Part Number: C0603X5R1C104K030BC
C28 = CAP_1: CAP CER 1UF 16V X5R 0402; Digikey P/N: 587-3709-2-ND; Manufacturer: Taiyo Yuden; Manufacturer Part Number: EMK105BJ105KVHF
J8 J51 J57 = CON3
J12 = J-HDR_1
J22 = J-HDR_0
PB2 PROGRAMN = T_POINT_R: Assy: DNI
Q1 = 2N2222_0: TRANS NPN 40V 0.6A SOT-23; Digikey P/N: MMBT2222ALT1HTSA1TR-ND; Manufacturer: Infineon Technologies; Manufacturer Part Number: MMBT2222ALT1HTSA1
Q7 = Q-BSS816NW_1: Manufacturer: Infineon Technologies; Manufacturer Part Number: BSS816NWH6327XTSA1
R20 R29 R94 = 5k1_0402: RES 4.70K OHM 1/10W 1% 0603 SMD; Digikey P/N: 541-4.70KHTR-ND; Manufacturer: Vishay; Manufacturer Part Number: CRCW06034K70FKEA
R22 R45 R64 R67 R75 R82 = R_330R_0603: Manufacturer Part Number: ERJ-3EKF3300V
R23 R30 = RES_10K_1W16_0402_5P: RES SMD 100 OHM 1% 1/10W 0402; Digikey P/N: RMCF0603JT10K0TR-ND; MFG: Pansonic; MFG P/N: ERJ-2RKF1000X; Manufacturer: Pansonic; Manufacturer Part Number: ERJ-2RKF1000X; Wattage: 1/10W
R25 R28 R121 = R: RES SMD 10K OHM 1% 1/16W 0402; Digikey P/N: 311-10.0KLRTR-ND; Manufacturer: Yageo; Manufacturer Part Number: RC0402FR-0710KL
R26 R27 R43 R44 R53-R57 R74 R76 = R0402_0.1R_1%_YAGEO: Manufacturer: Yageo; Manufacturer Part Number: RL0402FR-070R1L
R31 R117 = R: RES SMD 0 OHM JUMPER 1/16W 0402; Digikey P/N: 311-0.0JRTR-ND; Manufacturer: Yageo; Manufacturer Part Number: RC0402JR-070RL
R32 = RES_100K_1W16_0402_5P: RES SMD 1K OHM 1% 1/16W 0402; Digikey P/N: 311-1.00KLRTR-ND; Manufacturer: Yageo; Manufacturer Part Number: RC0402FR-071KL
R34 R95 R110 = R0402_10K_5%_VISHAY: Manufacturer: Vishay Dale; Manufacturer Part Number: CRCW040210K0JNED
R35 R37 R38 = R_v2: RES SMD 4.7K OHM 1% 1/16W 0402; DECOUPLER: NO; Digikey P/N: 311-4.7KLRTR-ND; MEMORY: NO; Manufacturer: Yageo; Manufacturer Part Number: RC0402FR-074K7L
R36 = R_v2: RES SMD 1K OHM 1% 1/16W 0402; Assy: DNI; DECOUPLER: NO; Digikey P/N: 311-1.00KLRTR-ND; MEMORY: NO; Manufacturer: Yageo; Manufacturer Part Number: RC0402FR-071KL
R92 R93 = R0402_4.7K_5%_VISHAY
SW1 SW2 = EVQP0_0: SWITCH TACTILE SPST-NO 0.05A 12V; Cost Ea/1k: $ 0.11025 (1000-4999), 0.09135 (5000+); Digikey P/N: CKN9112TR-ND; Distributor: Digi-Key; MFG: C&K Components; Manufacturer: C&K Components
U5 = U-W25Q512NWEIM_512Mb_Flash_2
C34 C35 C86 C108 = C-0402_0.1uF_10V_X5R_MURATA: Manufacturer: Murata Electronics; Manufacturer Part Number: GRM155R61A104KA01J
C105 = 10uF_0603: CAP CER 10UF 10V X5R 0402; Digikey P/N: 445-9065-2-ND; Manufacturer: Samsung; Manufacturer Part Number: CL05A106MP5NUNC
C106 C107 = CAP_NP_0: CAP CER 0.1UF 16V X5R 0201; Digikey P/N: 445-7313-2-ND; Manufacturer: TDK; Manufacturer Part Number: C0603X5R1C104K030BC
CN1 = CN-1-1734248-5_RPi: Manufacturer: TE Connectivity AMP Connectors
CN3 = CN-WP7A-S030VA1-R8000_Recpt: Manufacturer: JAE Electronics
D5 D7-D10 = LED_GREEN_0: Manufacturer Part Number: SML-D12M8WT86
FB1 FB11 = INDUCTOR_1: FERRITE BEAD 120 OHM 0402 1LN; Manufacturer: TDK Corporation
GPIO1 = T_POINT_R: Assy: DNL
Q2-Q5 = TRANS_NPN_45V_0_0.8A_SOT-23: TRANS NPN 45V 0.8A SOT-23; Manufacturer: Micro Commercial Co
R33 R116 = RESISTOR: RES 10K OHM 1/10W 5% 0603
R46 = R0402_0R_DNI_PANASONIC: Manufacturer: Panasonic Electronic Components; Manufacturer Part Number: ERJ-2GE0R00X
R47 R71 R79 R85 = R_10K_0603: Manufacturer Part Number: RC1608F103CS
R48-R51 = 5k1_0402: RES SMD 4.7K OHM 1% 1/16W 0402; Assy: DNI; Digikey P/N: 311-4.7KLRTR-ND; Manufacturer: Yageo; Manufacturer Part Number: RC0402FR-074K7L
U4 = LIFCL-33U-FCCSP104
U6 = U-PI4ULS3V204ZBEX: Manufacturer: Diodes Inc.
Y1 = Y-IQD_25MHz_50ppm_1.2V: Manufacturer: IQD Frequency Products
C44-C46 C48-C50 C54 C57 C76 C79 C82-C85 C104 = C-0201_0.1uF_10V_X5R_MURATA: Manufacturer: Murata; Manufacturer Part Number: GRM033R61A104ME15D
C93 = C-0402_0.1uF_10V_X5R_MURATA: Manufacturer: Murata Electronics
C94 = C-0402_4u7F_10V_TAIYO: Manufacturer: Taiyo Yuden
C95-C98 = C-0201_0.22uF_10V_X5R_MURATA: Manufacturer: Murata Electronics
C111 C112 = C-0201_0.22uF_10V_X5R_MURATA: Manufacturer: Murata Electronics; Manufacturer Part Number: GRM033R61A224KE90D
CN2 = CN-USB_TypeC_Recpt_R41_B583A_1: Manufacturer: Mitsumi Electric Company Ltd; Manufacturer Part Number: R41-B583A
FB2-FB5 = FB_1806_60R_BLM41PG600SN1L: Manufacturer: Murata Electronics; Manufacturer Part Number: BLM41PG600SN1L
FB6 FB7 FB9 = FB_0805_120R_BLM21PG121SN1D: Manufacturer: Murata Electronics; Manufacturer Part Number: BLM21PG121SN1D
R59 = R0402_300R_1%_YAGEO: Manufacturer: Yageo; Manufacturer Part Number: RC0402FR-07300RL
R60 = R0201_100R_1%_YAGEO: Assy: DNL; Manufacturer: Yageo; Manufacturer Part Number: RC0201FR-07100RL
R61 R89 R100 R118 R119 = R0402_4.7K_5%_VISHAY: Manufacturer: Vishay; Manufacturer Part Number: CRCW04024K70JNED
R97 = R0402_910K_1%_YAGEO: Manufacturer: YAGEO; Manufacturer Part Number: RC0402FR-07910KL
R98 = R0201_100R_1%_YAGEO: Manufacturer: Yageo; Manufacturer Part Number: RC0201FR-07100RL
R103-R106 R113 R114 = R0201_0R_1%_YAGEO: Manufacturer: Yageo; Manufacturer Part Number: RC0201JR-070RL
R107 R108 = R0402_10K_5%_YAGEO: Manufacturer: YAGEO; Manufacturer Part Number: RC0402JR-0710KL
R122 R123 = R: RES SMD 0 OHM JUMPER 1/16W 0402; Assy: DNL; Digikey P/N: 311-0.0JRTR-ND; Manufacturer: Yageo; Manufacturer Part Number: RC0402JR-070RL
U8 U9 U17 = SP3010-04UTG_1: TVS DIODE 6V 12.3V 10UDFN; Digikey P/N: F3507TR-ND; Manufacturer: Littelfuse Inc.
U14 = U-PI5USB30213AXEAEX_USB3_0
Y2 Y3 = Y_60MHZ_LVDS_Renesas: Manufacturer Part Number: XLL736060.000000I
Y4 = Y-ISM95-1251AH_60MHz_1.8V: Manufacturer: ILSI
C58 C88 = C_0.1uF_50V_CER_0402: Manufacturer Part Number: GRM155R71H104KE14J
C59 = C-0603_10uF_16V_X5R_TaiyoYuden: Manufacturer: Taiyo Yuden; Manufacturer Part Number: EMK107BBJ106MA-T
C60 C61 C90 C91 = C-0603_22uF_10V_X5R_Samsung: Manufacturer: Samsung Electro-Mechanics; Manufacturer Part Number: CL10A226MP8NUNE
C62 C63 = C-0201_0.1uF_6.3V_X5R_MURATA: Manufacturer: Murata; Manufacturer Part Number: GRM033R60J104KE19D
C65 C73 C80 C87 C89 = C_10uf_CER_25V_0603: CAP CER 10UF 25V X5R 0805; Manufacturer: TDK Corporation; Manufacturer Part No: C2012X5R1E106M085AC; Manufacturer Part Number: C2012X5R1E106M085AC
C66 C67 = 10uF_0603: CAP CER 10UF 16V X5R 0603; Digikey P/N: 445-9065-2-ND; Manufacturer: TDK Corporation; Manufacturer Part Number: C1608X5R1C106M080AB
C68-C72 = C-0201_0.1uF_6.3V_X5R_MURATA: MFG: Murata Electronics; Manufacturer: Murata Electronics; Manufacturer Part Number: GRM033R60J104KE19D
C75 C78 C81 = CAP_CER_100nF_0402_10V: CAP CER 10UF 16V X5R 0603; Digikey P/N: 445-9065-2-ND; Manufacturer: TDK Corporation; Manufacturer Part Number: C1608X5R1C106M080AB
FB8 FB10 = INDUCTOR_0: FERRITE BEAD 120 OHM 1206 1LN; Digikey P/N: 490-16524-2-ND; Manufacturer: Murata Electronics
J32-J35 = J-Turret: Manufacturer: Keystone Electronics; Manufacturer Part Number: 1573-2
L3 = L-3u3H_1.4A_BOURNS: Manufacturer: Bourns Inc.; Manufacturer Part Number: SRP2010DPA-3R3M
L6 = L-1u5H_2.1A_BOURNS: Manufacturer: Bourns Inc.; Manufacturer Part Number: SRP2010DPA-1R5M
MH1 MH2 = T_POINT_R_0: Assy: DNL
R62 R83 = R_42.2K_0402: RES SMD 18.2KOHM 0.1% 1/16W 0402; Manufacturer: YAGEO; Manufacturer Part No: RT0402BRD0718K2L; Manufacturer Part Number: RT0402BRD0718K2L
R63 = R0603_31K6_1%_Yageo: Manufacturer Part Number: RC0603FR-0731K6L
R65 R86 = R_12.7K_0402: Manufacturer Part Number: ERJ-2RKF1272X
R66 R87 = R0603_10K_1%_Yageo: Manufacturer Part Number: RC0603FR-0710KL
R68 = R0402_0R01_1%_YAGEO: Manufacturer: Yageo; Manufacturer Part Number: PE0402FRF070R01L
R84 = R0603_2K61_1%_Yageo: Manufacturer Part Number: RC0603FR-072K61L
U10 U13 = U-AP62201WU-7: Manufacturer: Diodes Incorporated
U11 = U-NCP177_LDO: Manufacturer: onsemi
U12 = U-NCP145_LDO: Manufacturer: onsemi

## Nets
GND: C1.2 C2.2 C3.2 C4.2 C5.2 C6.2 C7.2 C8.2 C9.2 C10.2 C11.2 C12.2 C13.2 C14.2 C15.2 C16.2 C17.2 C18.2 C19.2 C20.2 C21.2 C22.2 C24.2 C27.2 C28.2 C30.2 C31.2 C32.2 C33.2 C34.2 C35.2 C36.2 C43.2 C44.2 C45.2 C46.2 C47.2 C48.2 C49.2 C50.2 C51.2 C52.2 C53.2 C54.2 C55.2 C56.2 C57.2 C59.2 C60.2 C61.2 C62.2 C63.2 C65.2 C66.2 C67.2 C68.2 C69.2 C70.2 C71.2 C72.2 C73.2 C75.1 C76.2 C78.1 C79.2 C80.2 C81.1 C82.2 C83.2 C84.2 C85.2 C86.2 C87.2 C89.2 C90.2 C91.2 C92.2 C93.2 C94.2 C103.2 C104.2 C105.2 C106.2 C107.2 C108.2 C113.2 CN1.1(GND1) CN1.4(GND2) CN1.7(GND3) CN1.10(GND4) CN2.A1(GND1) CN2.A12(GND2) CN2.B1(GND3) CN2.B12(GND4) CN2.MH1 CN2.MH2 CN2.MH3 CN2.MH4 CN3.20(IO) CN3.22(IO) CN3.24(IO) CN3.27(IO) CN3.28(IO) CN3.29(IO) CN3.30(IO) D7.K D12.K(CATHODE) J1.7 J2.5(GND) J2.S1(CASE1) J2.S2(CASE2) J2.S3(CASE3) J2.S4(CASE4) J3.1 J5.1 J9.2 J12.6 J12.9 J12.10 J22.3 J23.1 J32.1 J33.1 J34.1 J35.1 J51.3 J56.1 J57.3 J59.2 MH1.1(TP) MH2.1(TP) Q1.E(EMITTER) Q2.E Q3.E Q4.E Q5.E R4.2 R5.2 R14.1 R46.2 R59.2 R65.2 R66.2 R86.2 R87.2 R89.2 R94.2 R107.2 R108.2 SW1.1(A1) SW1.3(A2) SW2.1(A1) SW2.3(A2) U1.1(GND) U2.1(GND) U2.5(GND_2) U2.10(AGND) U2.11(GND_3) U2.13(TEST) U2.15(GND_4) U2.25(GND_5) U2.35(GND_6) U2.47(GND_7) U2.51(GND_8) U3.5(VSS) U4.B5(AVSS_TX) U4.C2(VSS) U4.C4(VSS) U4.C6(AVSS) U4.D5(AVSS_COM) U4.D8(AVSS) U4.F3(VSS) U4.F5(VSS) U4.G4(VSS) U4.H3(VSS) U4.H5(VSS) U4.J4(VSS) U4.J7(VSS) U4.K5(VSS) U4.K8(VSS) U4.L1(VSS_AON) U5.4(GND) U5.9(EPAD) U6.7(GND) U8.3(GND2) U8.8(GND1) U9.3(GND2) U9.8(GND1) U10.1(GND) U11.2(GND) U11.5(EPAD) U12.5(GND) U13.1(GND) U14.25(GND) U17.3(GND2) U17.8(GND1) X1.2(GND) Y1.2(GND) Y2.3(GND) Y3.3(GND) Y4.2(GND)
V1P0_CORE: C62.1 C63.1 C66.1 C67.1 C68.1 C69.1 C70.1 C71.1 C72.1 J24.1 R68.2 U4.F4(VCC) U4.G3(VCC) U4.G5(VCC) U4.H4(VCC) U4.L2(VCC) U4.L5(VCC) U4.L8(VCC)
V1P8_AUX: FB10.2 J26.1 R76.2
V1P8_AUXA: FB8.2 J25.1 R74.2
VCC1_8FT: C1.1 C2.1 C3.1 C14.1 C15.1 U2.12(VCORE_1) U2.37(VCORE_2) U2.49(VREGOUT) U2.64(VCORE_3)
VCC_1V00: 1V0.1(TP) C90.1 C91.1 FB4.2 J24.2 L6.2 R68.1 R84.1 R85.2
VCC_1V20: 1V2.1(TP) C34.1 C87.1 J14.1 R44.1 R48.1 R49.1 R79.2 U6.1(VCCA) U6.8(EN) U12.1(OUT)
VCC_1V80: 1V8.1(TP) C73.1 FB2.2 FB5.2 FB7.1 FB9.1 J6.1 J13.1 J19.1 R26.1 R43.1 R56.1 R71.2 U11.1(OUT)
VCC_3V30: 3V3.1(TP) C4.1 C5.1 C6.1 C7.1 C8.1 C9.1 C17.1 C35.1 C36.1 C57.1 C60.1 C61.1 C65.1 C80.1 C86.1 C93.1 C94.1 C104.1 C105.1 C106.1 C107.1 C108.1 CN1.15(3V3) CN3.1(IO) CN3.2(IO) CN3.3(IO) FB3.1 J1.1 J7.1 L1.2 L2.2 L3.2 R1.1 R2.1 R3.1 R13.2 R16.1 R17.1 R18.1 R27.1 R45.2 R50.1 R51.1 R61.1 R63.1 R64.2 R67.2 R75.2 R82.2 R95.1 R100.1 R110.1 R118.1 R119.1 U2.20(VCCIO_1) U2.31(VCCIO_2) U2.42(VCCIO_3) U2.50(VREGIN) U2.56(VCCIO_4) U3.6(ORG) U3.8(VCC) U6.14(VCCB) U11.3(EN) U11.4(IN) U12.2(BIAS) U12.3(EN) U12.4(IN) U14.6(VDD) Y2.6(VDD) Y3.6(VDD)
VCC_5V00: 5V0.1(TP) C59.1 C89.1 D1.K D2.K R4.1 R62.1 R83.1 R91.1 U10.3(VIN) U13.3(VIN)
VCCIO0: C19.1 C20.1 C27.1 C28.1 J6.2 J12.2 Q7.G R20.1 R26.2 R34.1 R35.2 R36.2 R37.2 U4.C3(VCCIO0) U5.8(VCC)
VCCIO1: C21.1 C22.1 J7.2 J22.2 R22.2 R25.1 R27.2 R29.1 R32.2 R92.1 R93.1 R121.2 U4.C1(VCCIO1)
VCCIO2: C30.1 C31.1 J13.2 R43.2 U4.K4(VCCIO2)
VCCIO3: C32.1 C33.1 FB1.1 J14.2 R33.2 R44.2 U4.K6(VCCIO3)
VCCIO4: C52.1 C53.1 FB11.1 J19.2 R56.2 R116.2 U4.J8(VCCIO4)
ADDR: J51.2 U14.22(ADDR)
AON_INT: J21.2 R89.1 U4.N1(AON_INT)
AON_OUT: J21.1 U4.M1(AON_OUT)
CAM_CK_N: CN1.8(CSI_CK_N) U4.E6(PB14B/PCLKC3_1)
CAM_CK_P: CN1.9(CSI_CK_P) U4.F7(PB14A/PCLKT3_1)
CAM_D0_N: CN1.2(CSI_D0_N) U4.M6(PB10B/PCLKC3_0)
CAM_D0_P: CN1.3(CSI_D0_P) U4.M7(PB10A/PCLKT3_0)
CAM_D1_N: CN1.5(CSI_D1_N) U4.N6(PB8B)
CAM_D1_P: CN1.6(CSI_D1_P) U4.N7(PB8A/VREF3_1)
CAM_GPIO0_12: U4.L7(PB12A) U6.2(A1)
CAM_GPIO0_33: CN1.11(GPIO0) U6.13(B1)
CAM_GPIO1_12: U4.L6(PB12B) U6.3(A2)
CAM_GPIO1_33: GPIO1.1(TP) J31.1 U6.12(B2)
CAM_GPIO1_33_C: CN1.12(GPIO1) J31.2
CAM_SCL_12: R48.2 U4.J6(PB18A/PCLKT3_3/VREF3_2) U6.4(A3)
CAM_SCL_33: CN1.13(GPIO2) R50.2 U6.11(B3)
CAM_SDA_12: R49.2 U4.H6(PB18B/PCLKC3_3) U6.5(A4)
CAM_SDA_33: CN1.14(GPIO3) R51.2 U6.10(B4)
CC1: CN2.A5(CC1) U14.11(CC1)
CC2: CN2.B5(CC2) U14.12(CC2)
CSSPIN: J12.1 R34.2 R38.2 U4.B3(PT32B/MCSN)
DONE: R25.2 R28.2 U4.G2(PT48A/DONE)
DQ0_MOSI: J12.3 U4.D4(PT34A/MOSI/MD0) U5.5(DI/IO0)
DQ1_MISO: J12.5 U4.D3(PT34B/MISO/MD1) U5.2(DO/IO1)
DQ2: J12.7 R35.1 U4.E4(PT36A/MD2) U5.3(WP#/IO2)
DQ3: J12.4 J37.1 U4.E3(PT36B/MD3) U5.7(RESET#/IO3)
FPGA_SCL: J22.1 J29.2 R93.2 U4.E1(PT44B/SCL)
FPGA_SDA: J22.5 J30.2 J41.1 R92.2 U2.39(BDBUS1) U4.E2(PT44A/SDA)
FT_EECLK: R15.1 R17.2 U3.2(CLK)
FT_EECS: R16.2 U2.63(EECS) U3.1(CS)
FT_EEDATA: R19.1 U2.61(EEDATA) U3.3(DI)
FTDI_TCK: J1.8 R5.1 R6.2 U4.F2(PT46A/TCK/SCLK/PCLKT1_3/PMU_EXT_CLK)
FTDI_TDI: J1.3 R2.2 R9.2 U4.D2(PT42A/TDI/PCLKT1_1/OSC_HI/SSI)
FTDI_TDO: J1.2 R3.2 R7.2 U4.D1(PT42B/PCLKT1_2/TDO/SSO)
FTDI_TMS: J1.6 R1.2 R10.2 U4.B2(PT40A/TMS/SCSN/PCLKT1_0)
INITN_M_CEN: CN3.26(IO) INITN.1(TP) R121.1 U4.A1(PT38B/INITN)
JTAG_EN: J1.4 J8.2 J27.2 U4.A2(JTAG_EN)
LED0: R47.2 U4.G6(PB16B/PCLKC3_2)
M_ADQ0_PMA1: CN3.5(IO) U4.N5(PB32A/VREF2_1)
M_ADQ1_PMA2: CN3.6(IO) U4.N4(PB32B)
M_ADQ2_PMA3: CN3.7(IO) U4.M5(PB34A/PCLKT2_0)
M_ADQ3_PMA4: CN3.8(IO) U4.M4(PB34B/PCLKC2_0)
M_ADQ4_PMA7: CN3.9(IO) U4.L4(PB36A)
M_ADQ5_PMA8: CN3.10(IO) U4.L3(PB36B)
M_ADQ6_PMA9: CN3.11(IO) U4.N3(PB38A/PCLKT2_1)
M_ADQ7_PMA10: CN3.12(IO) U4.N2(PB38B/PCLKC2_1)
M_CLK_PMB9: CN3.21(IO) U4.J1(PB46A/PCLKT2_3)
M_DQ8_PMB1: CN3.14(IO) U4.M3(PB40A)
M_DQ9_PMB2: CN3.15(IO) U4.M2(PB40B)
M_DQ10_PMB3: CN3.16(IO) U4.K3(PB42A/PCLKT2_2)
M_DQ11_PMB4: CN3.17(IO) U4.K2(PB42B/PCLKC2_2)
M_DQ12_PMB7: CN3.18(IO) U4.J2(PB44A)
M_DQ13_PMB8: CN3.19(IO) U4.H2(PB44B)
M_DQ14_PMB10: CN3.23(IO) U4.H1(PB46B/PCLKC2_3/VREF2_2)
M_DQ15: CN3.25(IO) U4.N8(PB4A/LLC_GPLL0T_IN/VREF4_1)
M_DQS/DM0: CN3.4(IO) U4.A3(PT30B)
M_DQS/DM1: CN3.13(IO) U4.M8(PB4B/LLC_GPLL0C_IN)
OSC_25MHZ: U4.G7(PB16A/PCLKT3_2) Y1.3(OUTPUT)
OSC_60MHZ: R117.2 Y4.3(OUTPUT)
PROGRAMN_18: C18.1 J5.2 PROGRAMN.1(TP) Q7.S R20.2 R23.1 U4.A4(PT30A)
PROGRAMN_33: J28.2 Q7.D
PUSHBUTTON2: C103.1 PB2.1(TP) R29.2 R30.1 U4.B1(PT40B/MCSNO/MSDO)
RXD_UART: J22.6 J41.2 U4.G1(PT48B)
SPI_MCLK: J12.8 R31.2 R36.1 U5.6(CLK)
TXD_UART: J22.4 J40.2 U4.F1(PT46B/PMU_WAKEUP)
USB2_V5P0: C92.1 D2.A J2.1(VCC) U1.6(VBUS)
USB3_REFCLK_N: R60.2 R123.2 U4.G8(PB6B/PCLKC4_1/VREF4_2)
USB3_REFCLK_P: R60.1 R117.1 R122.2 U4.H8(PB6A/PCLKT4_1)
USB3_SS_RX1_N: CN2.B10(RX1-) R104.2 U8.2(IN/OUT2) U8.9(IN/OUT7)
USB3_SS_RX1_P: CN2.B11(RX1+) R103.2 U8.1(IN/OUT1) U8.10(IN/OUT8)
USB3_SS_RX2_N: CN2.A10(RX2-) R106.2 U17.1(IN/OUT1) U17.10(IN/OUT8)
USB3_SS_RX2_P: CN2.A11(RX2+) R105.2 U17.2(IN/OUT2) U17.9(IN/OUT7)
USB3_SS_TX1_N: C96.2 CN2.A3(TX1-) U8.5(IN/OUT4) U8.6(IN/OUT5)
USB3_SS_TX1_P: C95.2 CN2.A2(TX1+) U8.4(IN/OUT3) U8.7(IN/OUT6)
USB3_SS_TX2_N: C98.2 CN2.B3(TX2-) U17.4(IN/OUT3) U17.7(IN/OUT6)
USB3_SS_TX2_P: C97.2 CN2.B2(TX2+) U17.5(IN/OUT4) U17.6(IN/OUT5)
USB3_V5P0: C56.1 D1.A FB6.1 R97.2 U4.E5(VBUS)
USB_1V00: C49.1 C50.1 C51.1 J18.1 R55.2 U4.B7(AVDD) U4.C7(AVDD_TX)
USB_1V80: C43.1 C44.1 C45.1 C46.1 J16.1 R53.2 U4.B6(AVDD18) U4.C5(AVDD18_TX) U4.D6(AVDD18_COM)
USB_AON18: C54.1 C55.1 J20.1 R57.2 U4.K1(VCCAUX_AON)
USB_AVDD33: C47.1 C48.1 J17.2 R54.2 U4.A5(AVDD33)
USB_D_N: CN2.A7(D-) CN2.B7(D-) U4.E7(DM) U9.1(IN/OUT1) U9.10(IN/OUT8)
USB_D_P: CN2.A6(D+) CN2.B6(D+) U4.D7(DP) U9.2(IN/OUT2) U9.9(IN/OUT7)
USB_DM: J2.2(D-) U1.3(NC2) U1.4(D-) U2.7(DM)
USB_DP: J2.3(D+) U1.2(NC1) U1.5(D+) U2.8(DP)
USB_REFCLK_N: R98.2 U4.E8(REFIN_CLK_EXT_N) Y3.5(OUT#)
USB_REFCLK_P: R98.1 U4.F8(REFIN_CLK_EXT_P) Y3.4(OUT)
USB_RX_N: R113.2 U14.7(BN)
USB_RX_N_F: R113.1 U4.B8(RX_M)
USB_RX_P: R114.2 U14.8(BP)
USB_RX_P_F: R114.1 U4.A8(RX_P)
USB_SCL: J57.2 R119.2 U14.1(SCL_OUT2)
USB_SDA: J57.1 R118.2 U14.24(SDA_OUT1)
USB_TX_N: C111.2 U14.5(AN)
USB_TX_N_F: C111.1 U4.A6(TX_M)
USB_TX_P: C112.2 U14.4(AP)
USB_TX_P_F: C112.1 U4.A7(TX_P)
N16718169: R10.1 U2.19(ADBUS3)
N16718173: R6.1 U2.16(ADBUS0)
N16718177: R9.1 U2.17(ADBUS1)
N16718181: R7.1 U2.18(ADBUS2)
N16718361: C10.1 C11.1 L1.1 U2.9(VPLL)
N16718365: C12.1 C13.1 L2.1 U2.4(VPHY)
N16718405: R18.2 R19.2 U3.4(DO)
N16718621: R14.2 U2.6(REF)
N16718649: R15.2 U2.62(EECLK)
N16718725: C16.1 J3.2 R13.1 U2.14(RESET#)
N16774276: J37.2 R37.1
N16774410: R38.1 U5.1(CS#)
N16775593: D4.K(CATHODE) Q1.C(COLLECTOR)
N16775643: D4.A(ANODE) R22.1
N17566020: U2.2(OSCI) X1.1(IN)
N17672962: 12MHZ.1(TP) U2.3(OSCO) X1.3(OUT)
N17836253: J8.3 R94.1
N17836312: J8.1 R32.1
N17905156: J27.1 U2.21(ADBUS4)
N18009731: Q1.B(BASE) R28.1
N18064922: R59.1 U4.C8(REXT23)
N18065947: FB3.2 J17.1 R54.1
N18066741: FB5.1 J20.2 R57.1
N18074742: FB2.1 J16.2 R53.1
N18077501: FB4.1 J18.2 R55.1
N18095006: R31.1 U4.B4(PT32A/MCLK)
N18095240: R23.2 SW1.2(B1) SW1.4(B2)
N18098678: J28.1 U2.24(ADBUS7)
N18110652: R46.1 U6.15(EPad)
N18122025: C58.1 U10.6(BST)
N18122072: C58.2 L3.1 U10.2(SW)
N18122138: R62.2 R65.1 U10.5(EN)
N18122148: R63.2 R66.1 U10.4(FB)
N18122154: D7.A R64.1
N18122509: D10.A R82.1
N18122519: C88.1 U13.6(BST)
N18122570: C88.2 L6.1 U13.2(SW)
N18122606: D10.K Q5.C
N18122632: R83.2 R86.1 U13.5(EN)
N18122642: R84.2 R87.1 U13.4(FB)
N18122677: Q5.B R85.1
N18123053: D9.A R75.1
N18123150: D9.K Q4.C
N18123221: Q4.B R79.1
N18132561: J23.2 R61.2 Y2.1(E/D)
N18143826: C78.2 C79.1 C81.2 C82.1 C83.1 C84.1 C85.1 FB10.1 U4.F6(VCCAUX) U4.J3(VCCAUX) U4.J5(VCCAUX) U4.K7(VCCAUX)
N18144525: FB9.2 J26.2 R76.1
N18147832: D5.A R45.1
N18147842: D5.K Q2.C
N18147863: Q2.B R47.1
N18148551: FB7.2 J25.2 R74.1
N18148595: C75.2 C76.1 FB8.1 U4.H7(VCCAUX)
N18185281: R30.2 SW2.2(B1) SW2.4(B2)
N18199487: D8.A R67.1
N18199519: D8.K Q3.C
N18199568: Q3.B R71.1
N18225426: J9.1 R33.1 Y1.1(STANDBY)
N18225446: C24.1 FB1.2 Y1.4(VDD)
N18265639: D12.A(ANODE) R91.2
N18271195: J29.1 J40.1 U2.38(BDBUS0)
N18277889: CN2.A4(VBUS1) CN2.A9(VBUS2) CN2.B4(VBUS3) CN2.B9(VBUS4) FB6.2
N18280818: C95.1 U14.16(A1P)
N18280935: C96.1 U14.17(AIN)
N18280941: C98.1 U14.20(A2N)
N18284351: J51.1 R95.2
N18307740: J56.2 R100.2 Y3.1(E/D)
N18321347: C97.1 U14.21(A2P)
N18321374: R103.1 U14.14(B1P)
N18321388: R104.1 U14.15(B1N)
N18321404: R105.1 U14.19(B2P)
N18321418: R106.1 U14.18(B2N)
N18326769: R107.1 U14.13(ENB)
N18327261: R108.1 U14.3(PORT)
N18331463: R110.2 U14.9(ID)
N18332454: R97.1 U14.23(VBUSDET)
N18341385: J59.1 R116.1 Y4.1(STANDBY)
N18341405: C113.1 FB11.2 Y4.4(VDD)
N18357184: J30.1 U2.40(BDBUS2)
N18391348: R122.1 Y2.4(OUT)
N18391443: R123.1 Y2.5(OUT#)

Not connected (* = marked no-connect by the designer): CN2 A8(SBU1)* B8(SBU2)*; J1 5*; J2 4(ID)*; U2 22(ADBUS5)* 23(ADBUS6)* 26(ACBUS0)* 27(ACBUS1)* 28(ACBUS2)* 29(ACBUS3)* 30(ACBUS4)* 32(ACBUS5)* 33(ACBUS6)* 34(ACBUS7)* 36(SUSPEND#)* 41(BDBUS3)* 43(BDBUS4)* 44(BDBUS5)* 45(BDBUS6)* 46(BDBUS7)* 48(BCBUS0)* 52(BCBUS1)* 53(BCBUS2)* 54(BCBUS3)* 55(BCBUS4)* 57(BCBUS5)* 58(BCBUS6)* 59(BCBUS7)* 60(PWREN#)*; U3 7(NU)*; U6 6(NC)* 9(NC1)*; U9 4(IN/OUT3)* 5(IN/OUT4)* 6(IN/OUT5)* 7(IN/OUT6)*; U14 2(INTB_OUT3)* 10(VCONN)*; Y2 2(NC)*; Y3 2(NC)*

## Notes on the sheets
sheet 1
- CrossLink-NX-33U Evaluation Board Revision History
- Revision B
  --- Initial Release
sheet 2
- CrossLinkU-NX Evaluation Board
                  LIFCL-33U-EVN
                          Rev - B.1
- 01 - Title Page
  02 - Block Diagram
  03 - FTDI, UART, USB2 Interface
  04 - Flash, JTAG, DB, UART, Pushbutton
  05 - DB Connector, Raspberry Pi Camera Connector, LED & 25MHz OSC
  06 - DB Connector, USB Ref Clock, USB3 Interface
  07 - Power
  08 - Power Diagram
  09 - Revision History
sheet 4
- DONE indicator will light when
  configuration is successfully
  completed
- PROGRAMN
- DONE
- Default:
  J5 - OPEN
- Default:
  J6 - OPEN
- Default:
  J7 - OPEN
- Bank0
- Bank1
- Default:
  1-2
- VCCIO0 = 1.8V
- VCCIO1 = 3.3V
- Flash Debug Header
- DNI
- Place between Flash
  & LIFCL-33U
- Default:
  J37 - CLOSED
- I2C Debug Header
- 512Mb SPI Flash
- Flash Replacement Option:
      GD25LQ128ESIGR
sheet 5
- Default:
  J13 - OPEN
- Default:
  J14 - OPEN
- Bank2
- Bank3
- DNI
- DNI
- DNI
- DNI
- VCCIO2 = 1.8V
- VCCIO3 = 1.2V
sheet 6
- Default:
  J16 - OPEN
- Default:
  J17 - OPEN
- Default:
  J18 - OPEN
- Default:
  J19 - OPEN
- ESD
- Bank4
- Default:
  J20 - OPEN
- Default:
  J56 - CLOSED
- VCCIO4 = 1.8V
- Default:
  J21 - OPEN
- Do not populate components in dotted box.
  See LIFLCL-33U-EVN-REVB.2 schematic for changes.
- Default:
  J23 - CLOSED
- USB 3.0 TYPE-C
  CONNECTOR
- Default:
  J59 - OPEN
- Default:
  J51 = OPEN
  **************************************
  J51 = Float: Pin Control Mode
  J51 = 1-2: I2C Enable & ADDR Bit 6 = 1
  J51 = 2-3: I2C Enable & ADDR Bit 6 = 0
sheet 7
- Output = 3.30V
- 5V-3.3V
- Default:
  J24 - OPEN
- Output = 1.80V
- Default:
  J25 - OPEN
- 3.3V-1.8V
- Default:
  J26 - OPEN
- Output = 1.20V
- 3.3V-1.2V
- For securing the daughter
  board to the connector.
- Output = 1.00V
- 5V-1V
sheet 9
- Place near pin VREGIN
- Micro USB
- Default:
  J3 - OPEN
- Default:
  J27 - OPEN
  J28 - OPEN
  J40 - CLOSED
  J41 - CLOSED
  J29 - OPEN
  J30 - OPEN
